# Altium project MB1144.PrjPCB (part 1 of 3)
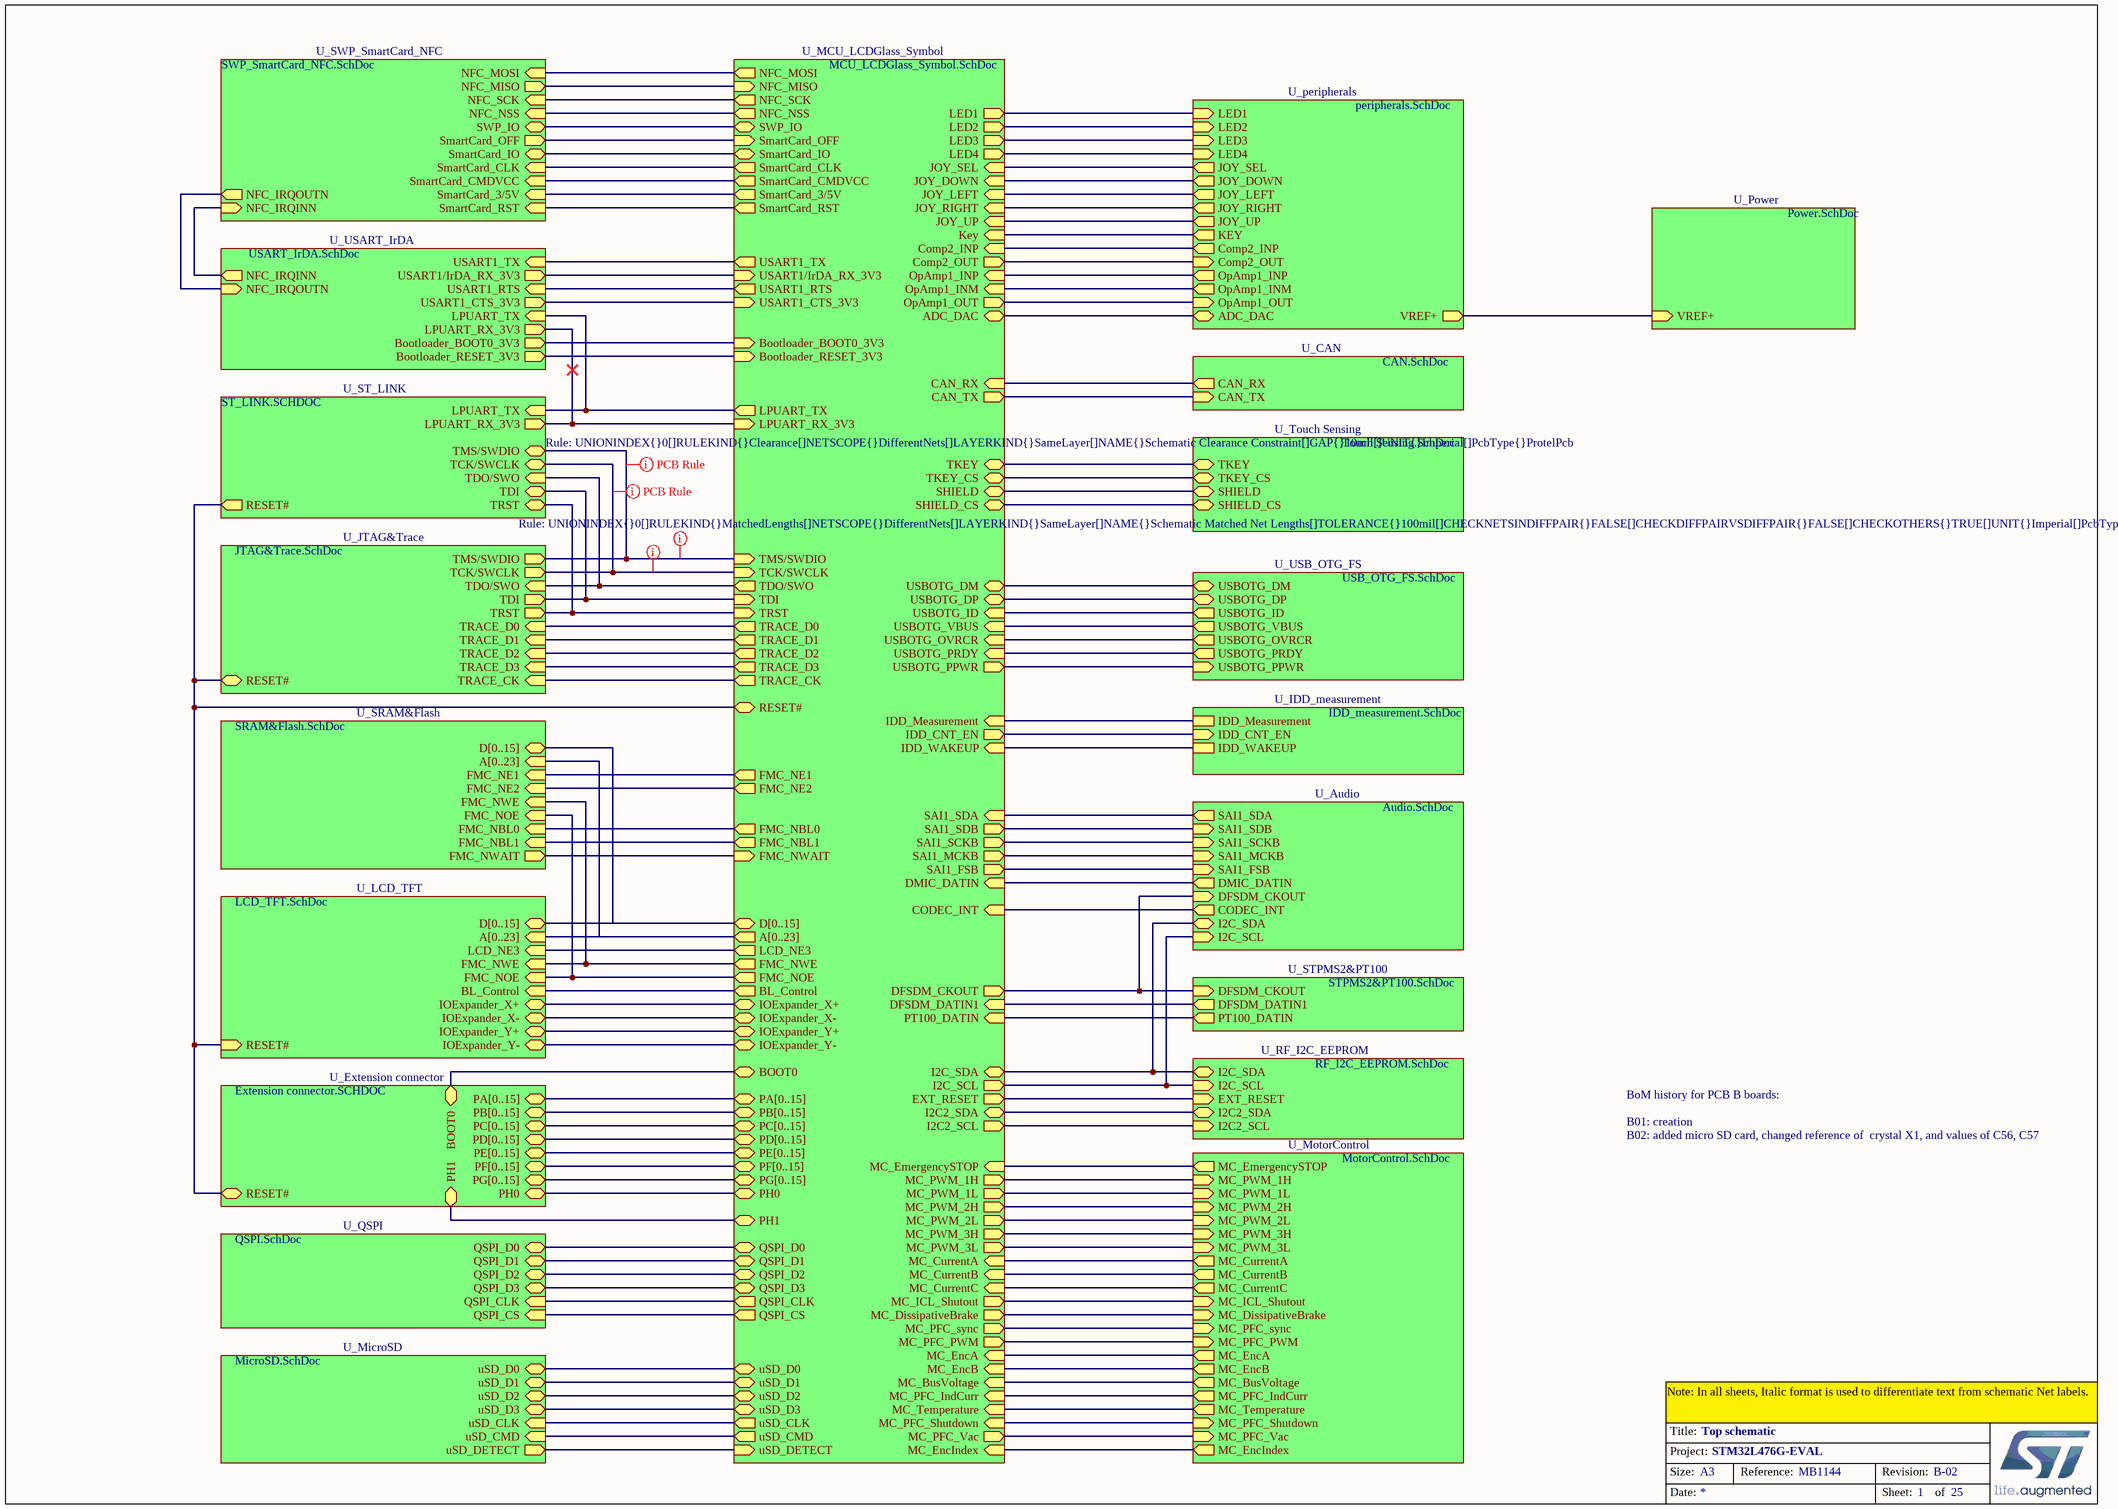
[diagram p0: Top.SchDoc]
25 sheets, 601 parts. Net scope: hierarchical (ports join the sheet entries above them; power ports are global).
Sheets:
  Top.SchDoc
    U_MCU_LCDGlass_Symbol = MCU_LCDGlass_Symbol.SchDoc
      U_MCU = MCU.SchDoc
      U_LCD_Glass = LCD_Glass.SchDoc
      U_IO_Expandor = IO_Expandor.SchDoc
      U_MCU2 = MCU2.SchDoc
    U_SRAM&Flash = SRAM&Flash.SchDoc
    U_MotorControl = MotorControl.SchDoc
    U_MicroSD = MicroSD.SchDoc
    U_QSPI = QSPI.SchDoc
    U_Extension connector = Extension connector.SCHDOC
    U_JTAG&Trace = JTAG&Trace.SchDoc
    U_ST_LINK = ST_LINK.SCHDOC
    U_USART_IrDA = USART_IrDA.SchDoc
    U_SWP_SmartCard_NFC = SWP_SmartCard_NFC.SchDoc
    U_STPMS2&PT100 = STPMS2&PT100.SchDoc
    U_IDD_measurement = IDD_measurement.SchDoc
    U_USB_OTG_FS = USB_OTG_FS.SchDoc
    U_Touch Sensing = Touch Sensing.SchDoc
    U_CAN = CAN.SchDoc
    U_peripherals = peripherals.SchDoc
    U_Power = Power.SchDoc
    U_Audio = Audio.SchDoc
    U_LCD_TFT = LCD_TFT.SchDoc
    U_RF_I2C_EEPROM = RF_I2C_EEPROM.SchDoc

## Sheet Top.SchDoc: Top schematic
size A3; DocumentNumber: MB1144; Revision: B-02; SheetNumber: 1; SheetTotal: 25; PageSetup: Record=PageOptions|CenterHorizontal=True|CenterVertical=True|PrintScale=1.01|XCorrection=1.00|YCorrection=1.00|PrintKind=1|BorderSize=5000000|LeftOffset=0|BottomOffset=0|Orientation=2|PaperLength=1000|PaperWidth=1000|Scale=100|PaperSource=264|PrintQuality=600|MediaType=1|DitherType=10|PaperKind=A3|PrintScaleMode=1; Project: STM32L476G-EVAL

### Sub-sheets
U_Audio = Audio.SchDoc: SAI1_SCKB (in), SAI1_FSB (in), SAI1_SDB (in), CODEC_INT (out), I2C_SCL (in), SAI1_MCKB (in), I2C_SDA (bidir), DMIC_DATIN (out), DFSDM_CKOUT (in), SAI1_SDA (out)
U_CAN = CAN.SchDoc: CAN_TX (in), CAN_RX (out)
U_Extension connector = Extension connector.SCHDOC: PA[0..15] (bidir), PB[0..15] (bidir), PC[0..15] (bidir), PD[0..15] (bidir), PE[0..15] (bidir), RESET# (bidir), PF[0..15] (bidir), PG[0..15] (bidir), PH1, PH0, BOOT0
U_IDD_measurement = IDD_measurement.SchDoc: IDD_Measurement, IDD_CNT_EN (in), IDD_WAKEUP
U_JTAG&Trace = JTAG&Trace.SchDoc: TDI (out), RESET# (bidir), TRACE_D3 (in), TRACE_D2 (in), TRACE_D1 (in), TRACE_D0 (in), TRACE_CK (in), TRST (out), TMS/SWDIO (out), TCK/SWCLK (out), TDO/SWO (in)
U_LCD_TFT = LCD_TFT.SchDoc: RESET# (in), FMC_NWE (in), LCD_NE3 (in), FMC_NOE (in), D[0..15] (bidir), A[0..23] (in), IOExpander_Y+ (bidir), IOExpander_Y- (bidir), IOExpander_X+ (bidir), IOExpander_X- (bidir), BL_Control (in)
U_MCU_LCDGlass_Symbol = MCU_LCDGlass_Symbol.SchDoc: FMC_NWAIT (in), FMC_NOE (out), FMC_NWE (out), FMC_NE1 (out), FMC_NE2 (out), LCD_NE3 (out), LED1 (out), LED2 (out), LPUART_TX (out), USART1_TX (out), USART1_RTS (out), TMS/SWDIO (in), TCK/SWCLK (in), TDI (in), TRST (in), Key (in), DFSDM_DATIN1 (in), IDD_Measurement (in), CODEC_INT (in), USBOTG_PRDY (in), USBOTG_OVRCR (in), DMIC_DATIN (in), PT100_DATIN (in), USBOTG_VBUS (in), USBOTG_ID (in), IDD_WAKEUP (in), OpAmp1_INM (in), Comp2_INP (in), TDO/SWO (out), TRACE_D1 (out), TRACE_D2 (out), TRACE_D3 (out), IDD_CNT_EN (out), USBOTG_PPWR (out), TRACE_CK (out), TRACE_D0 (out), SmartCard_CLK (out), OpAmp1_OUT (out), ADC_DAC (bidir), USBOTG_DP (bidir), USBOTG_DM (bidir), SmartCard_IO (bidir), QSPI_D0 (bidir), QSPI_D1 (bidir), QSPI_D2 (bidir), QSPI_D3 (bidir), uSD_D0 (bidir), uSD_D1 (bidir), uSD_D2 (bidir), uSD_D3 (bidir), MC_DissipativeBrake (out), MC_PFC_sync (out), MC_PWM_1H (out), MC_PWM_1L (out), MC_PWM_2H (out), MC_PWM_2L (out), MC_PWM_3H (out), MC_PWM_3L (out), MC_ICL_Shutout (out), MC_PFC_PWM (out), MC_PFC_Vac (out), QSPI_CLK (out), QSPI_CS (out), FMC_NBL0 (out), FMC_NBL1 (out), CAN_TX (out), MC_EncA (in), MC_EncB (in), MC_EncIndex (in), MC_CurrentB (in), MC_CurrentC (in), MC_Temperature (in), MC_PFC_Shutdown (in), CAN_RX (in), uSD_DETECT (in), uSD_CMD (out), uSD_CLK (out), SWP_IO (bidir), IOExpander_X+ (bidir), IOExpander_X- (bidir), IOExpander_Y+ (bidir), IOExpander_Y- (bidir), JOY_SEL (in), JOY_DOWN (in), JOY_LEFT (in), JOY_RIGHT (in), JOY_UP (in), SmartCard_OFF (in), LED4 (out), LED3 (out), SmartCard_RST (out), SmartCard_CMDVCC (out), SmartCard_3/5V (out), D[0..15] (bidir), A[0..23] (out), PA[0..15] (bidir), PB[0..15] (bidir), PC[0..15] (bidir), PD[0..15] (bidir), PE[0..15] (bidir), PF[0..15] (bidir), PG[0..15] (bidir), MC_CurrentA (in), MC_EmergencySTOP (in), MC_BusVoltage (in), MC_PFC_IndCurr (in), RESET# (bidir), DFSDM_CKOUT (out), I2C_SCL (out), I2C_SDA (bidir), PH1, PH0, SHIELD, SAI1_MCKB (out), SAI1_SCKB (out), SAI1_FSB (out), SAI1_SDB (out), SAI1_SDA (in), OpAmp1_INP (in), Comp2_OUT (out), TKEY, TKEY_CS, SHIELD_CS, Bootloader_RESET_3V3 (in), Bootloader_BOOT0_3V3 (in), LPUART_RX_3V3 (in), USART1_CTS_3V3 (in), USART1/IrDA_RX_3V3 (in), BL_Control (out), EXT_RESET (out), BOOT0, NFC_NSS (out), NFC_MOSI (out), NFC_SCK (out), NFC_MISO (in), I2C2_SDA (bidir), I2C2_SCL (out)
U_MicroSD = MicroSD.SchDoc: uSD_CLK (in), uSD_CMD (in), uSD_D0 (bidir), uSD_D1 (bidir), uSD_D2 (bidir), uSD_D3 (bidir), uSD_DETECT (out)
U_MotorControl = MotorControl.SchDoc: MC_EmergencySTOP (out), MC_CurrentA (out), MC_CurrentB (out), MC_CurrentC (out), MC_PFC_sync (in), MC_PWM_3L (in), MC_PWM_2H (in), MC_PWM_2L (in), MC_PWM_1H (in), MC_PWM_1L (in), MC_PWM_3H (in), MC_ICL_Shutout (in), MC_DissipativeBrake (in), MC_PFC_PWM (in), MC_EncA (out), MC_EncB (out), MC_BusVoltage (out), MC_EncIndex (out), MC_PFC_IndCurr (out), MC_Temperature (out), MC_PFC_Shutdown (in), MC_PFC_Vac (in)
U_peripherals = peripherals.SchDoc: ADC_DAC (bidir), LED4 (in), LED3 (in), LED1 (in), LED2 (in), JOY_SEL (out), JOY_DOWN (out), JOY_LEFT (out), JOY_RIGHT (out), JOY_UP (out), KEY (out), VREF+ (out), Comp2_INP (out), OpAmp1_OUT (in), OpAmp1_INM (out), OpAmp1_INP (out), Comp2_OUT (in)
U_Power = Power.SchDoc: VREF+ (in)
U_QSPI = QSPI.SchDoc: QSPI_D0 (bidir), QSPI_D3 (bidir), QSPI_D2 (bidir), QSPI_D1 (bidir), QSPI_CLK (in), QSPI_CS (in)
U_RF_I2C_EEPROM = RF_I2C_EEPROM.SchDoc: I2C_SCL (in), I2C_SDA (bidir), EXT_RESET (in), I2C2_SDA (bidir), I2C2_SCL (in)
U_SRAM&Flash = SRAM&Flash.SchDoc: FMC_NWE (in), FMC_NOE (in), FMC_NWAIT (out), FMC_NBL0 (in), FMC_NBL1 (in), D[0..15] (bidir), A[0..23] (in), FMC_NE1 (in), FMC_NE2 (in)
U_ST_LINK = ST_LINK.SCHDOC: TDO/SWO (in), RESET# (out), TDI, TRST, TMS/SWDIO, TCK/SWCLK, LPUART_RX_3V3 (out), LPUART_TX (in)
U_STPMS2&PT100 = STPMS2&PT100.SchDoc: DFSDM_CKOUT (in), DFSDM_DATIN1 (out), PT100_DATIN (out)
U_SWP_SmartCard_NFC = SWP_SmartCard_NFC.SchDoc: SWP_IO (bidir), SmartCard_3/5V (in), SmartCard_IO (bidir), SmartCard_RST (in), SmartCard_CLK (in), SmartCard_OFF (out), SmartCard_CMDVCC (in), NFC_IRQINN (in), NFC_IRQOUTN (out), NFC_NSS (in), NFC_MOSI (in), NFC_MISO (out), NFC_SCK (in)
U_Touch Sensing = Touch Sensing.SchDoc: SHIELD, SHIELD_CS, TKEY_CS, TKEY
U_USART_IrDA = USART_IrDA.SchDoc: USART1/IrDA_RX_3V3 (out), Bootloader_BOOT0_3V3 (out), Bootloader_RESET_3V3 (out), USART1_CTS_3V3 (out), USART1_TX (in), USART1_RTS (in), LPUART_RX_3V3 (out), LPUART_TX (in), NFC_IRQINN (out), NFC_IRQOUTN (in)
U_USB_OTG_FS = USB_OTG_FS.SchDoc: USBOTG_VBUS (out), USBOTG_PRDY (out), USBOTG_DM (bidir), USBOTG_DP (bidir), USBOTG_OVRCR (out), USBOTG_PPWR (in), USBOTG_ID (out)

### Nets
BOOT0: sheet U_MCU_LCDGlass_Symbol/BOOT0, sheet U_Extension connector/BOOT0
Comp2_INP: sheet U_MCU_LCDGlass_Symbol/Comp2_INP, sheet U_peripherals/Comp2_INP
Comp2_OUT: sheet U_MCU_LCDGlass_Symbol/Comp2_OUT, sheet U_peripherals/Comp2_OUT
I2C_SCL: sheet U_MCU_LCDGlass_Symbol/I2C_SCL, sheet U_Audio/I2C_SCL, sheet U_RF_I2C_EEPROM/I2C_SCL
I2C_SDA: sheet U_MCU_LCDGlass_Symbol/I2C_SDA, sheet U_Audio/I2C_SDA, sheet U_RF_I2C_EEPROM/I2C_SDA
LCD_NE3: sheet U_MCU_LCDGlass_Symbol/LCD_NE3, sheet U_LCD_TFT/LCD_NE3
LCDSEG7: sheet U_MCU_LCDGlass_Symbol/TDO/SWO, sheet U_JTAG&Trace/TDO/SWO, sheet U_ST_LINK/TDO/SWO
LCDSEG8: sheet U_MCU_LCDGlass_Symbol/TRST, sheet U_JTAG&Trace/TRST, sheet U_ST_LINK/TRST
LCDSEG17: sheet U_MCU_LCDGlass_Symbol/TDI, sheet U_JTAG&Trace/TDI, sheet U_ST_LINK/TDI
OpAmp1_INM: sheet U_MCU_LCDGlass_Symbol/OpAmp1_INM, sheet U_peripherals/OpAmp1_INM
OpAmp1_INP: sheet U_MCU_LCDGlass_Symbol/OpAmp1_INP, sheet U_peripherals/OpAmp1_INP
OpAmp1_OUT: sheet U_MCU_LCDGlass_Symbol/OpAmp1_OUT, sheet U_peripherals/OpAmp1_OUT
PA4: sheet U_MCU_LCDGlass_Symbol/ADC_DAC, sheet U_peripherals/ADC_DAC
PA11: sheet U_MCU_LCDGlass_Symbol/USBOTG_DM, sheet U_USB_OTG_FS/USBOTG_DM
PA12: sheet U_MCU_LCDGlass_Symbol/USBOTG_DP, sheet U_USB_OTG_FS/USBOTG_DP
PA13: sheet U_MCU_LCDGlass_Symbol/TMS/SWDIO, sheet U_JTAG&Trace/TMS/SWDIO, sheet U_ST_LINK/TMS/SWDIO
PA14: sheet U_MCU_LCDGlass_Symbol/TCK/SWCLK, sheet U_JTAG&Trace/TCK/SWCLK, sheet U_ST_LINK/TCK/SWCLK
PB6: sheet U_MCU_LCDGlass_Symbol/USART1_TX, sheet U_USART_IrDA/USART1_TX
PC13: sheet U_MCU_LCDGlass_Symbol/Key, sheet U_peripherals/KEY
PD3: sheet U_MCU_LCDGlass_Symbol/DFSDM_DATIN1, sheet U_STPMS2&PT100/DFSDM_DATIN1
PD4: sheet U_MCU_LCDGlass_Symbol/FMC_NOE, sheet U_SRAM&Flash/FMC_NOE, sheet U_LCD_TFT/FMC_NOE
PD5: sheet U_MCU_LCDGlass_Symbol/FMC_NWE, sheet U_SRAM&Flash/FMC_NWE, sheet U_LCD_TFT/FMC_NWE
PD7: sheet U_MCU_LCDGlass_Symbol/FMC_NE1, sheet U_SRAM&Flash/FMC_NE1
PF11: sheet U_MCU_LCDGlass_Symbol/NFC_NSS, sheet U_SWP_SmartCard_NFC/NFC_NSS
PG8: sheet U_MCU_LCDGlass_Symbol/LPUART_RX_3V3, sheet U_ST_LINK/LPUART_RX_3V3, sheet U_USART_IrDA/LPUART_RX_3V3
PG9: sheet U_MCU_LCDGlass_Symbol/FMC_NE2, sheet U_SRAM&Flash/FMC_NE2
PG11: sheet U_MCU_LCDGlass_Symbol/USART1_CTS_3V3, sheet U_USART_IrDA/USART1_CTS_3V3
PG12: sheet U_MCU_LCDGlass_Symbol/USART1_RTS, sheet U_USART_IrDA/USART1_RTS
PH0: sheet U_MCU_LCDGlass_Symbol/PH0, sheet U_Extension connector/PH0
PH1: sheet U_MCU_LCDGlass_Symbol/PH1, sheet U_Extension connector/PH1
RESET#: sheet U_MCU_LCDGlass_Symbol/RESET#, sheet U_Extension connector/RESET#, sheet U_JTAG&Trace/RESET#, sheet U_ST_LINK/RESET#, sheet U_LCD_TFT/RESET#
NetB3_1: sheet U_MCU_LCDGlass_Symbol/JOY_LEFT, sheet U_peripherals/JOY_LEFT
NetB3_2: sheet U_MCU_LCDGlass_Symbol/JOY_SEL, sheet U_peripherals/JOY_SEL
NetB3_3: sheet U_MCU_LCDGlass_Symbol/JOY_DOWN, sheet U_peripherals/JOY_DOWN
NetB3_4: sheet U_MCU_LCDGlass_Symbol/JOY_RIGHT, sheet U_peripherals/JOY_RIGHT
NetB3_6: sheet U_MCU_LCDGlass_Symbol/JOY_UP, sheet U_peripherals/JOY_UP
NetC1_2: sheet U_MCU_LCDGlass_Symbol/MC_EncB, sheet U_MotorControl/MC_EncB
NetC2_2: sheet U_MCU_LCDGlass_Symbol/MC_EncIndex, sheet U_MotorControl/MC_EncIndex
NetC3_1: sheet U_MCU_LCDGlass_Symbol/MC_PFC_IndCurr, sheet U_MotorControl/MC_PFC_IndCurr
NetC4_2: sheet U_MCU_LCDGlass_Symbol/MC_EncA, sheet U_MotorControl/MC_EncA
NetC5_2: sheet U_MCU_LCDGlass_Symbol/MC_PFC_Shutdown, sheet U_MotorControl/MC_PFC_Shutdown
NetC6_2: sheet U_MCU_LCDGlass_Symbol/MC_PFC_Vac, sheet U_MotorControl/MC_PFC_Vac
NetC7_2: sheet U_MCU_LCDGlass_Symbol/MC_EmergencySTOP, sheet U_MotorControl/MC_EmergencySTOP
NetC9_2: sheet U_MCU_LCDGlass_Symbol/MC_PFC_PWM, sheet U_MotorControl/MC_PFC_PWM
NetC10_2: sheet U_MCU_LCDGlass_Symbol/MC_CurrentC, sheet U_MotorControl/MC_CurrentC
NetC11_1: sheet U_MCU_LCDGlass_Symbol/MC_BusVoltage, sheet U_MotorControl/MC_BusVoltage
NetC13_2: sheet U_MCU_LCDGlass_Symbol/MC_CurrentB, sheet U_MotorControl/MC_CurrentB
NetC14_2: sheet U_MCU_LCDGlass_Symbol/MC_CurrentA, sheet U_MotorControl/MC_CurrentA
NetC15_1: sheet U_MCU_LCDGlass_Symbol/USBOTG_PRDY, sheet U_MCU_LCDGlass_Symbol/USBOTG_VBUS, sheet U_USB_OTG_FS/USBOTG_VBUS, sheet U_USB_OTG_FS/USBOTG_PRDY
NetC16_2: sheet U_MCU_LCDGlass_Symbol/MC_PFC_sync, sheet U_MotorControl/MC_PFC_sync
NetC17_1: sheet U_MCU_LCDGlass_Symbol/MC_Temperature, sheet U_MotorControl/MC_Temperature
NetC34_2: sheet U_MCU_LCDGlass_Symbol/SHIELD_CS, sheet U_Touch Sensing/SHIELD_CS
NetC37_2: sheet U_MCU_LCDGlass_Symbol/TKEY_CS, sheet U_Touch Sensing/TKEY_CS
NetC52_2: sheet U_peripherals/VREF+, sheet U_Power/VREF+
NetC73_1: sheet U_MCU_LCDGlass_Symbol/IDD_Measurement, sheet U_IDD_measurement/IDD_Measurement
NetCN2_3: sheet U_MCU_LCDGlass_Symbol/MC_PWM_1H, sheet U_MotorControl/MC_PWM_1H
NetCN2_5: sheet U_MCU_LCDGlass_Symbol/MC_PWM_1L, sheet U_MotorControl/MC_PWM_1L
NetCN2_7: sheet U_MCU_LCDGlass_Symbol/MC_PWM_2H, sheet U_MotorControl/MC_PWM_2H
NetCN2_9: sheet U_MCU_LCDGlass_Symbol/MC_PWM_2L, sheet U_MotorControl/MC_PWM_2L
NetCN2_11: sheet U_MCU_LCDGlass_Symbol/MC_PWM_3H, sheet U_MotorControl/MC_PWM_3H
NetCN2_13: sheet U_MCU_LCDGlass_Symbol/MC_PWM_3L, sheet U_MotorControl/MC_PWM_3L
NetCN2_21: sheet U_MCU_LCDGlass_Symbol/MC_ICL_Shutout, sheet U_MotorControl/MC_ICL_Shutout
NetCN2_23: sheet U_MCU_LCDGlass_Symbol/MC_DissipativeBrake, sheet U_MotorControl/MC_DissipativeBrake
NetCN3_4: sheet U_MCU_LCDGlass_Symbol/EXT_RESET, sheet U_RF_I2C_EEPROM/EXT_RESET
NetCN11_4: sheet U_MCU_LCDGlass_Symbol/uSD_DETECT, sheet U_MicroSD/uSD_DETECT
NetCN11_6: sheet U_MCU_LCDGlass_Symbol/USBOTG_ID, sheet U_USB_OTG_FS/USBOTG_ID
NetCN11_8: sheet U_MCU_LCDGlass_Symbol/CAN_TX, sheet U_CAN/CAN_TX
NetCN11_16: sheet U_MCU_LCDGlass_Symbol/NFC_MISO, sheet U_SWP_SmartCard_NFC/NFC_MISO
NetCN11_18: sheet U_MCU_LCDGlass_Symbol/NFC_SCK, sheet U_SWP_SmartCard_NFC/NFC_SCK
NetCN11_20: sheet U_MCU_LCDGlass_Symbol/SWP_IO, sheet U_SWP_SmartCard_NFC/SWP_IO
NetCN11_24: sheet U_MCU_LCDGlass_Symbol/CAN_RX, sheet U_CAN/CAN_RX
NetCN11_26: sheet U_MCU_LCDGlass_Symbol/NFC_MOSI, sheet U_SWP_SmartCard_NFC/NFC_MOSI
NetCN11_28: sheet U_MCU_LCDGlass_Symbol/DFSDM_CKOUT, sheet U_STPMS2&PT100/DFSDM_CKOUT, sheet U_Audio/DFSDM_CKOUT
NetCN11_30: sheet U_MCU_LCDGlass_Symbol/LED3, sheet U_peripherals/LED3
NetCN11_32: sheet U_MCU_LCDGlass_Symbol/DMIC_DATIN, sheet U_Audio/DMIC_DATIN
NetCN12_12: sheet U_MCU_LCDGlass_Symbol/TRACE_CK, sheet U_JTAG&Trace/TRACE_CK
NetCN12_18: sheet U_MCU_LCDGlass_Symbol/TRACE_D2, sheet U_JTAG&Trace/TRACE_D2
NetCN12_20: sheet U_MCU_LCDGlass_Symbol/TRACE_D3, sheet U_JTAG&Trace/TRACE_D3
NetCN13_1: sheet U_USART_IrDA/NFC_IRQOUTN, sheet U_SWP_SmartCard_NFC/NFC_IRQOUTN
NetCN13_2: sheet U_USART_IrDA/NFC_IRQINN, sheet U_SWP_SmartCard_NFC/NFC_IRQINN
NetCN14_2: sheet U_MCU_LCDGlass_Symbol/uSD_CMD, sheet U_MicroSD/uSD_CMD
NetCN14_10: sheet U_MCU_LCDGlass_Symbol/USART1/IrDA_RX_3V3, sheet U_USART_IrDA/USART1/IrDA_RX_3V3
NetCN14_40: sheet U_MCU_LCDGlass_Symbol/FMC_NBL0, sheet U_SRAM&Flash/FMC_NBL0
NetCN14_42: sheet U_MCU_LCDGlass_Symbol/FMC_NBL1, sheet U_SRAM&Flash/FMC_NBL1
NetCN18_1: sheet U_MCU_LCDGlass_Symbol/uSD_D2, sheet U_MicroSD/uSD_D2
NetCN18_2: sheet U_MCU_LCDGlass_Symbol/uSD_D3, sheet U_MicroSD/uSD_D3
NetCN18_5: sheet U_MCU_LCDGlass_Symbol/uSD_CLK, sheet U_MicroSD/uSD_CLK
NetCN18_7: sheet U_MCU_LCDGlass_Symbol/uSD_D0, sheet U_MicroSD/uSD_D0
NetCN18_8: sheet U_MCU_LCDGlass_Symbol/uSD_D1, sheet U_MicroSD/uSD_D1
NetCN19_31: sheet U_MCU_LCDGlass_Symbol/IOExpander_X-, sheet U_LCD_TFT/IOExpander_X-
NetCN19_32: sheet U_MCU_LCDGlass_Symbol/IOExpander_X+, sheet U_LCD_TFT/IOExpander_X+
NetCN19_33: sheet U_MCU_LCDGlass_Symbol/IOExpander_Y-, sheet U_LCD_TFT/IOExpander_Y-
NetCN19_34: sheet U_MCU_LCDGlass_Symbol/IOExpander_Y+, sheet U_LCD_TFT/IOExpander_Y+
NetD4_2: sheet U_MCU_LCDGlass_Symbol/Bootloader_RESET_3V3, sheet U_USART_IrDA/Bootloader_RESET_3V3
NetJP19_1: sheet U_MCU_LCDGlass_Symbol/USBOTG_PPWR, sheet U_USB_OTG_FS/USBOTG_PPWR
NetLD6_2: sheet U_MCU_LCDGlass_Symbol/USBOTG_OVRCR, sheet U_USB_OTG_FS/USBOTG_OVRCR
NetR24_1: sheet U_MCU_LCDGlass_Symbol/PT100_DATIN, sheet U_STPMS2&PT100/PT100_DATIN
NetR32_2: sheet U_MCU_LCDGlass_Symbol/FMC_NWAIT, sheet U_SRAM&Flash/FMC_NWAIT
NetR34_1: sheet U_MCU_LCDGlass_Symbol/LPUART_TX, sheet U_ST_LINK/LPUART_TX, sheet U_USART_IrDA/LPUART_TX
NetR35_1: sheet U_MCU_LCDGlass_Symbol/CODEC_INT, sheet U_Audio/CODEC_INT
NetR37_1: sheet U_MCU_LCDGlass_Symbol/SHIELD, sheet U_Touch Sensing/SHIELD
NetR39_1: sheet U_MCU_LCDGlass_Symbol/TKEY, sheet U_Touch Sensing/TKEY
NetR53_2: sheet U_MCU_LCDGlass_Symbol/SAI1_SDA, sheet U_Audio/SAI1_SDA
NetR54_2: sheet U_MCU_LCDGlass_Symbol/LED1, sheet U_peripherals/LED1
NetR59_2: sheet U_MCU_LCDGlass_Symbol/Bootloader_BOOT0_3V3, sheet U_USART_IrDA/Bootloader_BOOT0_3V3
NetR71_2: sheet U_MCU_LCDGlass_Symbol/QSPI_CS, sheet U_QSPI/QSPI_CS
NetR89_1: sheet U_MCU_LCDGlass_Symbol/SAI1_SCKB, sheet U_Audio/SAI1_SCKB
NetR90_1: sheet U_MCU_LCDGlass_Symbol/SAI1_FSB, sheet U_Audio/SAI1_FSB
NetR91_1: sheet U_MCU_LCDGlass_Symbol/IDD_CNT_EN, sheet U_IDD_measurement/IDD_CNT_EN
NetR104_1: sheet U_MCU_LCDGlass_Symbol/TRACE_D0, sheet U_JTAG&Trace/TRACE_D0
NetR105_1: sheet U_MCU_LCDGlass_Symbol/SAI1_SDB, sheet U_Audio/SAI1_SDB
NetR106_1: sheet U_MCU_LCDGlass_Symbol/SAI1_MCKB, sheet U_Audio/SAI1_MCKB
NetR107_1: sheet U_MCU_LCDGlass_Symbol/SmartCard_CLK, sheet U_SWP_SmartCard_NFC/SmartCard_CLK
NetR137_1: sheet U_MCU_LCDGlass_Symbol/IDD_WAKEUP, sheet U_IDD_measurement/IDD_WAKEUP
NetR143_1: sheet U_MCU_LCDGlass_Symbol/SmartCard_IO, sheet U_SWP_SmartCard_NFC/SmartCard_IO
NetR156_2: sheet U_MCU_LCDGlass_Symbol/TRACE_D1, sheet U_JTAG&Trace/TRACE_D1
NetR213_1: sheet U_MCU_LCDGlass_Symbol/SmartCard_OFF, sheet U_SWP_SmartCard_NFC/SmartCard_OFF
NetR214_2: sheet U_MCU_LCDGlass_Symbol/SmartCard_RST, sheet U_SWP_SmartCard_NFC/SmartCard_RST
NetR215_2: sheet U_MCU_LCDGlass_Symbol/SmartCard_CMDVCC, sheet U_SWP_SmartCard_NFC/SmartCard_CMDVCC
NetR241_1: sheet U_MCU_LCDGlass_Symbol/SmartCard_3/5V, sheet U_SWP_SmartCard_NFC/SmartCard_3/5V
NetR255_1: sheet U_MCU_LCDGlass_Symbol/LED4, sheet U_peripherals/LED4
NetR257_1: sheet U_MCU_LCDGlass_Symbol/LED2, sheet U_peripherals/LED2
NetR260_1: sheet U_MCU_LCDGlass_Symbol/BL_Control, sheet U_LCD_TFT/BL_Control
NetR263_2: sheet U_MCU_LCDGlass_Symbol/I2C2_SDA, sheet U_RF_I2C_EEPROM/I2C2_SDA
NetR264_2: sheet U_MCU_LCDGlass_Symbol/I2C2_SCL, sheet U_RF_I2C_EEPROM/I2C2_SCL
NetSB9_1: sheet U_MCU_LCDGlass_Symbol/QSPI_CLK, sheet U_QSPI/QSPI_CLK
NetSB12_1: sheet U_MCU_LCDGlass_Symbol/QSPI_D0, sheet U_QSPI/QSPI_D0
NetSB14_1: sheet U_MCU_LCDGlass_Symbol/QSPI_D1, sheet U_QSPI/QSPI_D1
NetSB18_1: sheet U_MCU_LCDGlass_Symbol/QSPI_D2, sheet U_QSPI/QSPI_D2
NetSB21_1: sheet U_MCU_LCDGlass_Symbol/QSPI_D3, sheet U_QSPI/QSPI_D3

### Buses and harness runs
bus sheet U_Extension connector/PA[0..15] = sheet U_MCU_LCDGlass_Symbol/PA[0..15]
bus sheet U_Extension connector/PB[0..15] = sheet U_MCU_LCDGlass_Symbol/PB[0..15]
bus sheet U_Extension connector/PC[0..15] = sheet U_MCU_LCDGlass_Symbol/PC[0..15]
bus sheet U_Extension connector/PD[0..15] = sheet U_MCU_LCDGlass_Symbol/PD[0..15]
bus sheet U_Extension connector/PE[0..15] = sheet U_MCU_LCDGlass_Symbol/PE[0..15]
bus sheet U_Extension connector/PF[0..15] = sheet U_MCU_LCDGlass_Symbol/PF[0..15]
bus sheet U_Extension connector/PG[0..15] = sheet U_MCU_LCDGlass_Symbol/PG[0..15]
bus sheet U_LCD_TFT/A[0..23] = sheet U_MCU_LCDGlass_Symbol/A[0..23] = sheet U_SRAM&Flash/A[0..23]
bus sheet U_LCD_TFT/D[0..15] = sheet U_MCU_LCDGlass_Symbol/D[0..15] = sheet U_SRAM&Flash/D[0..15]

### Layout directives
rule Matched Net Lengths [Tolerance = 100mil]: PA13, PA14
rule Clearance Constraint [Clearance = 10mil]: PA13, PA14

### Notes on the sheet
- BoM history for PCB B boards:
  B01: creation
  B02: added micro SD card, changed reference of  crystal X1, and values of C56, C57
- Note: In all sheets, Italic format is used to differentiate text from schematic Net labels.

## Sheet MCU_LCDGlass_Symbol.SchDoc: MCU_LCDGlassl
size A3; DocumentNumber: MB1144; Revision: B-02; SheetNumber: 2; SheetTotal: 25; PageSetup: Record=PageOptions|CenterHorizontal=True|CenterVertical=True|PrintScale=1.01|XCorrection=1.00|YCorrection=1.00|PrintKind=1|BorderSize=5000000|LeftOffset=0|BottomOffset=0|Orientation=2|PaperLength=1000|PaperWidth=1000|Scale=100|PaperSource=264|PrintQuality=600|MediaType=1|DitherType=10|PaperKind=A3|PrintScaleMode=1; Project: STM32L476G-EVAL
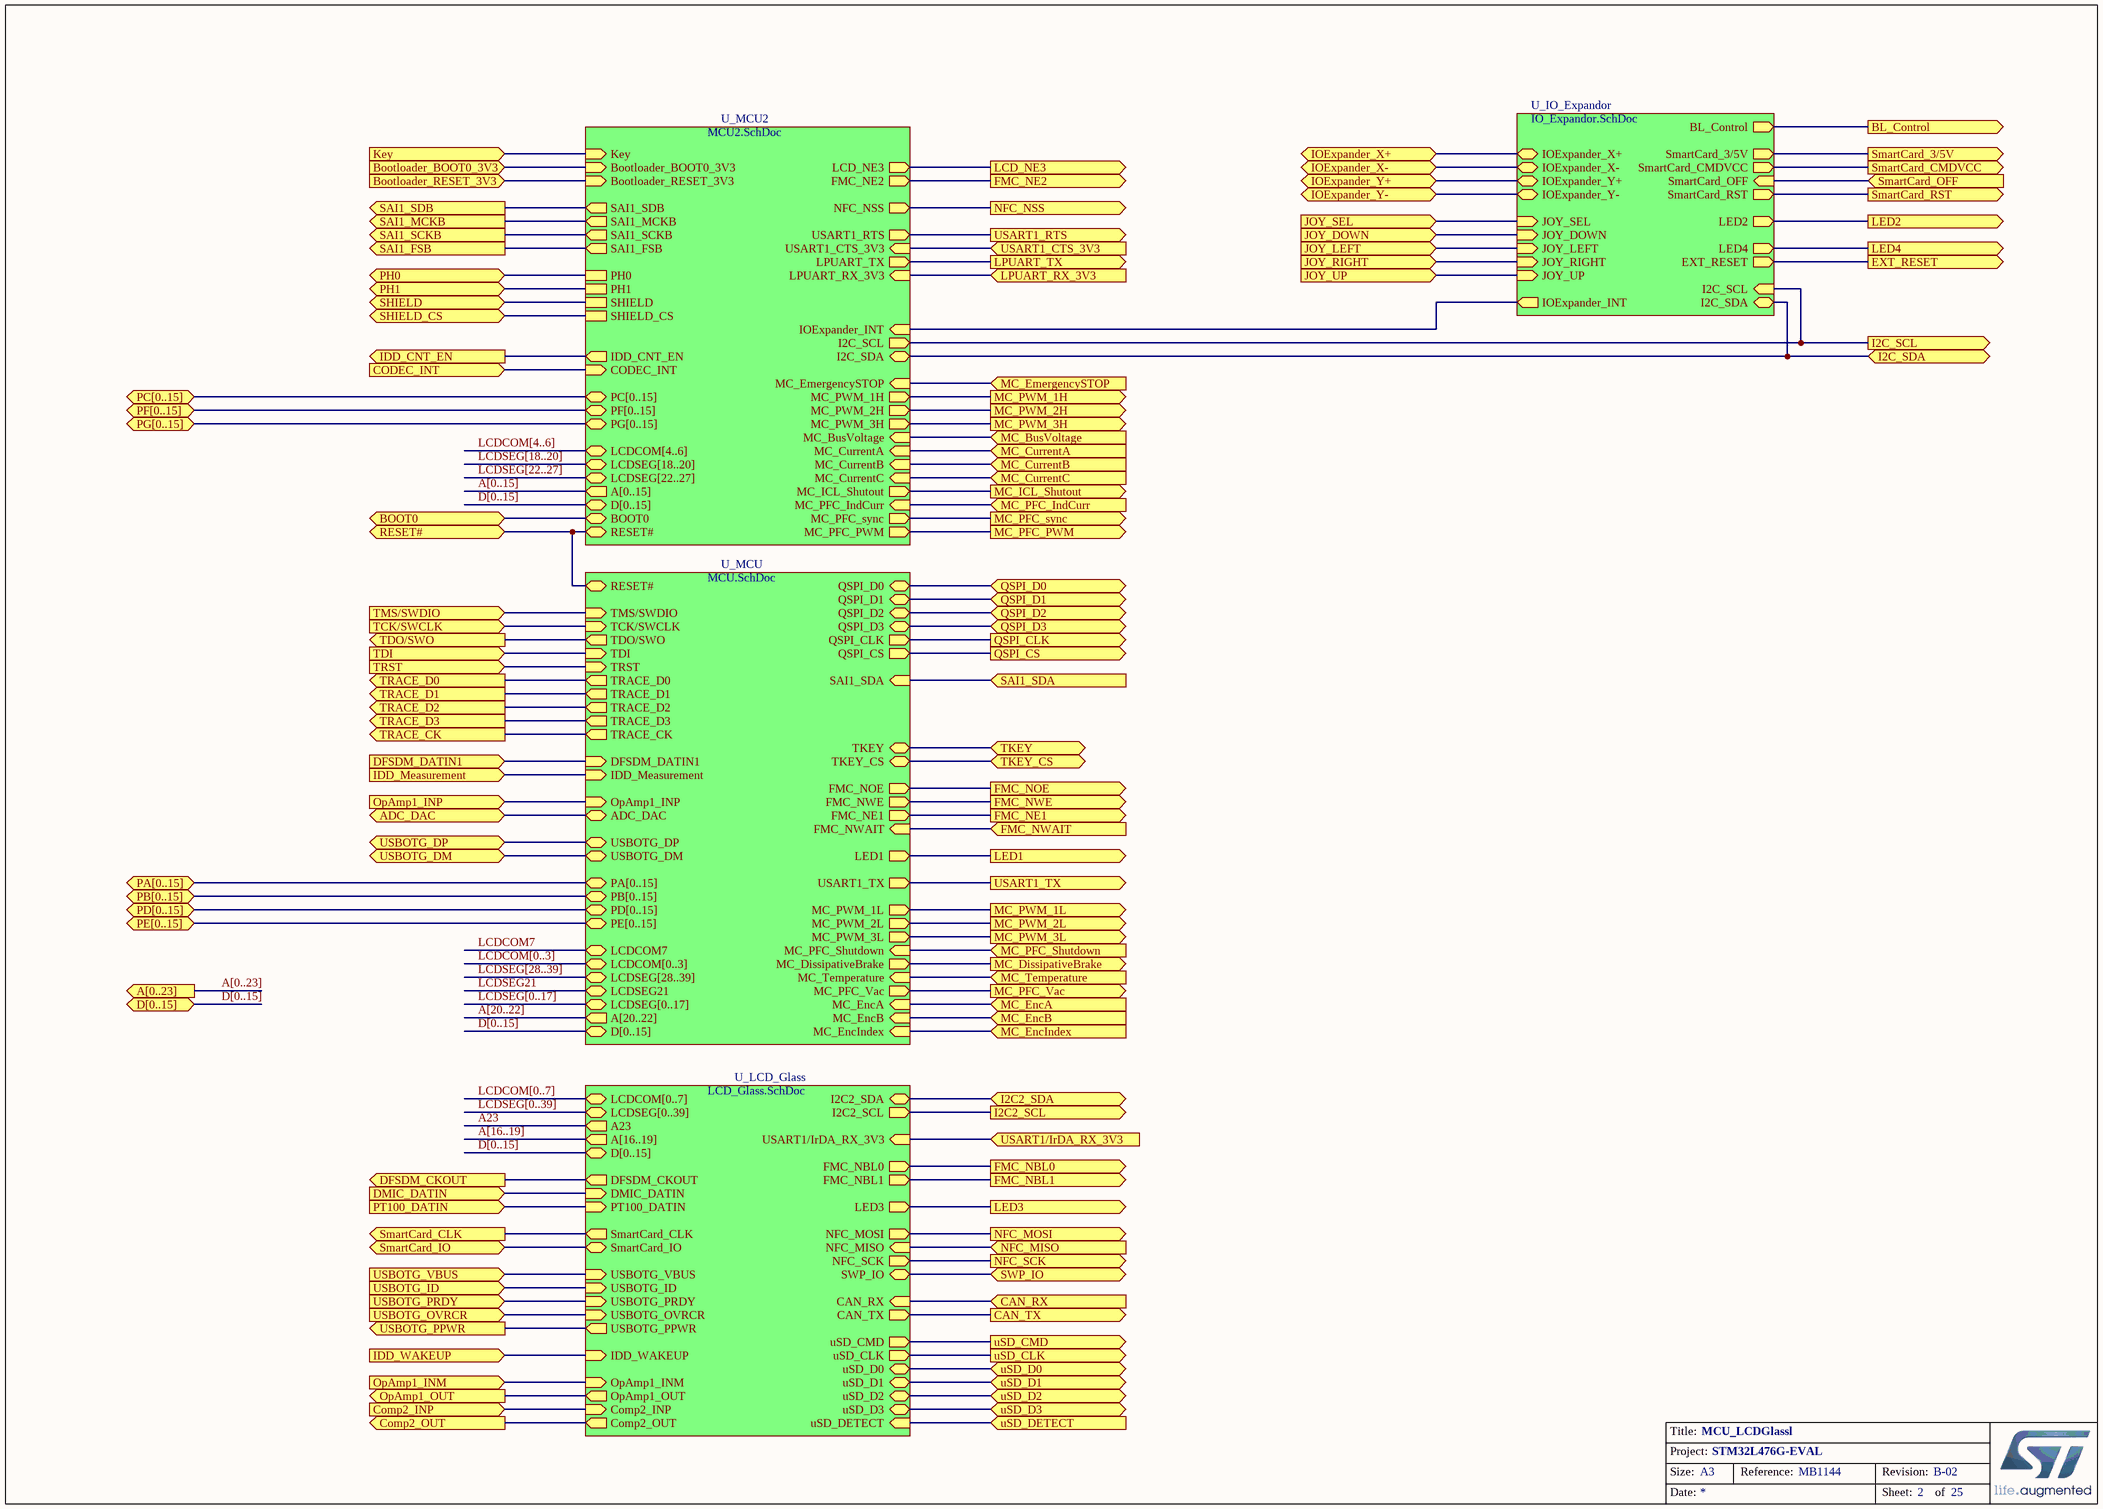
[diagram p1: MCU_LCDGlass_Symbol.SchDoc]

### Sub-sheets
U_IO_Expandor = IO_Expandor.SchDoc: IOExpander_Y+ (bidir), IOExpander_Y- (bidir), IOExpander_X+ (bidir), IOExpander_X- (bidir), IOExpander_INT (out), I2C_SDA (bidir), JOY_SEL (in), JOY_DOWN (in), JOY_LEFT (in), JOY_RIGHT (in), JOY_UP (in), LED4 (out), SmartCard_RST (out), SmartCard_CMDVCC (out), SmartCard_3/5V (out), SmartCard_OFF (in), I2C_SCL (in), LED2 (out), BL_Control (out), EXT_RESET (out)
U_LCD_Glass = LCD_Glass.SchDoc: uSD_CMD (out), uSD_CLK (out), uSD_D3 (bidir), uSD_D2 (bidir), IDD_WAKEUP (in), PT100_DATIN (in), uSD_D0 (bidir), uSD_D1 (bidir), OpAmp1_INM (in), FMC_NBL0 (out), FMC_NBL1 (out), LCDSEG[0..39] (bidir), LCDCOM[0..7] (bidir), USBOTG_VBUS (in), USBOTG_ID (in), CAN_TX (out), SWP_IO (bidir), CAN_RX (in), DMIC_DATIN (in), OpAmp1_OUT (out), Comp2_INP (in), SmartCard_CLK (out), SmartCard_IO (bidir), uSD_DETECT (in), DFSDM_CKOUT (out), D[0..15] (bidir), USBOTG_PRDY (in), USBOTG_OVRCR (in), USBOTG_PPWR (out), Comp2_OUT (out), USART1/IrDA_RX_3V3 (in), A[16..19] (out), A23 (out), NFC_MISO (in), NFC_SCK (out), NFC_MOSI (out), I2C2_SDA (bidir), I2C2_SCL (out), LED3 (out)
U_MCU = MCU.SchDoc: PA[0..15] (bidir), PB[0..15] (bidir), PD[0..15] (bidir), PE[0..15] (bidir), USBOTG_DM (bidir), USBOTG_DP (bidir), TMS/SWDIO (in), TCK/SWCLK (in), DFSDM_DATIN1 (in), FMC_NOE (out), FMC_NWE (out), FMC_NWAIT (in), FMC_NE1 (out), TRACE_D3 (out), TRACE_D1 (out), TRST (in), D[0..15] (bidir), IDD_Measurement (in), USART1_TX (out), LED1 (out), MC_DissipativeBrake (out), TRACE_D2 (out), MC_EncA (in), TDI (in), TDO/SWO (out), ADC_DAC (bidir), RESET# (bidir), QSPI_D3 (bidir), QSPI_D2 (bidir), QSPI_D1 (bidir), QSPI_D0 (bidir), QSPI_CLK (out), QSPI_CS (out), TRACE_D0 (out), TRACE_CK (out), SAI1_SDA (in), OpAmp1_INP (in), MC_PFC_Vac (out), MC_Temperature (in), MC_EncB (in), MC_EncIndex (in), TKEY, TKEY_CS, MC_PWM_1L (out), MC_PWM_2L (out), MC_PWM_3L (out), MC_PFC_Shutdown (in), A[20..22] (out), LCDCOM[0..3] (bidir), LCDCOM7, LCDSEG[0..17] (bidir), LCDSEG[28..39] (bidir), LCDSEG21 (bidir)
U_MCU2 = MCU2.SchDoc: PC[0..15] (bidir), Bootloader_BOOT0_3V3 (in), Bootloader_RESET_3V3 (in), Key (in), CODEC_INT (in), USART1_CTS_3V3 (in), FMC_NE2 (out), USART1_RTS (out), PF[0..15] (bidir), PG[0..15] (bidir), D[0..15] (bidir), MC_PFC_sync (out), IDD_CNT_EN (out), LPUART_TX (out), LPUART_RX_3V3 (in), LCD_NE3 (out), IOExpander_INT (in), I2C_SCL (out), I2C_SDA (bidir), RESET# (bidir), PH1, PH0, SHIELD, SAI1_SDB (out), SAI1_MCKB (out), SAI1_SCKB (out), SAI1_FSB (out), MC_ICL_Shutout (out), MC_PFC_PWM (out), MC_CurrentB (in), MC_CurrentC (in), MC_CurrentA (in), MC_PFC_IndCurr (in), MC_BusVoltage (in), MC_PWM_1H (out), SHIELD_CS, MC_PWM_2H (out), MC_PWM_3H (out), MC_EmergencySTOP (in), A[0..15] (out), LCDSEG[18..20] (bidir), LCDCOM[4..6] (bidir), LCDSEG[22..27] (bidir), BOOT0, NFC_NSS (out)

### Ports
A[0..23] (out), ADC_DAC (bidir), BL_Control (out), BOOT0, Bootloader_BOOT0_3V3 (in), Bootloader_RESET_3V3 (in), CAN_RX (in), CAN_TX (out), CODEC_INT (in), Comp2_INP (in), Comp2_OUT (out), D[0..15] (bidir), DFSDM_CKOUT (out), DFSDM_DATIN1 (in), DMIC_DATIN (in), EXT_RESET (out), FMC_NBL0 (out), FMC_NBL1 (out), FMC_NE1 (out), FMC_NE2 (out), FMC_NOE (out), FMC_NWAIT (in), FMC_NWE (out), I2C2_SCL (out), I2C2_SDA (bidir), I2C_SCL (out), I2C_SDA (bidir), IDD_CNT_EN (out), IDD_Measurement (in), IDD_WAKEUP (in), IOExpander_X+ (bidir), IOExpander_X- (bidir), IOExpander_Y+ (bidir), IOExpander_Y- (bidir), JOY_DOWN (in), JOY_LEFT (in), JOY_RIGHT (in), JOY_SEL (in), JOY_UP (in), Key (in), LCD_NE3 (out), LED1 (out), LED2 (out), LED3 (out), LED4 (out), LPUART_RX_3V3 (in), LPUART_TX (out), MC_BusVoltage (in), MC_CurrentA (in), MC_CurrentB (in), MC_CurrentC (in), MC_DissipativeBrake (out), MC_EmergencySTOP (in), MC_EncA (in), MC_EncB (in), MC_EncIndex (in), MC_ICL_Shutout (out), MC_PFC_IndCurr (in), MC_PFC_PWM (out), MC_PFC_Shutdown (in), MC_PFC_sync (out), MC_PFC_Vac (out), MC_PWM_1H (out), MC_PWM_1L (out), MC_PWM_2H (out), MC_PWM_2L (out), MC_PWM_3H (out), MC_PWM_3L (out), MC_Temperature (in), NFC_MISO (in), NFC_MOSI (out), NFC_NSS (out), NFC_SCK (out), OpAmp1_INM (in), OpAmp1_INP (in), OpAmp1_OUT (out), PA[0..15] (bidir), PB[0..15] (bidir), PC[0..15] (bidir), PD[0..15] (bidir), PE[0..15] (bidir), PF[0..15] (bidir), PG[0..15] (bidir), PH0, PH1, PT100_DATIN (in), QSPI_CLK (out), QSPI_CS (out), QSPI_D0 (bidir), QSPI_D1 (bidir), QSPI_D2 (bidir), QSPI_D3 (bidir), RESET# (bidir), SAI1_FSB (out), SAI1_MCKB (out), SAI1_SCKB (out), SAI1_SDA (in), SAI1_SDB (out), SHIELD, SHIELD_CS, SmartCard_3/5V (out), SmartCard_CLK (out), SmartCard_CMDVCC (out), SmartCard_IO (bidir), SmartCard_OFF (in), SmartCard_RST (out), SWP_IO (bidir), TCK/SWCLK (in), TDI (in), TDO/SWO (out), TKEY, TKEY_CS, TMS/SWDIO (in), TRACE_CK (out), TRACE_D0 (out), TRACE_D1 (out), TRACE_D2 (out), TRACE_D3 (out), TRST (in), USART1/IrDA_RX_3V3 (in), USART1_CTS_3V3 (in), USART1_RTS (out), USART1_TX (out), USBOTG_DM (bidir), USBOTG_DP (bidir), USBOTG_ID (in), USBOTG_OVRCR (in), USBOTG_PPWR (out), USBOTG_PRDY (in), USBOTG_VBUS (in), uSD_CLK (out), uSD_CMD (out), uSD_D0 (bidir), uSD_D1 (bidir), uSD_D2 (bidir), uSD_D3 (bidir), uSD_DETECT (in)

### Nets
BOOT0: port BOOT0, sheet U_MCU2/BOOT0
Comp2_INP: port Comp2_INP, sheet U_LCD_Glass/Comp2_INP
Comp2_OUT: port Comp2_OUT, sheet U_LCD_Glass/Comp2_OUT
I2C_SCL: port I2C_SCL, sheet U_IO_Expandor/I2C_SCL, sheet U_MCU2/I2C_SCL
I2C_SDA: port I2C_SDA, sheet U_IO_Expandor/I2C_SDA, sheet U_MCU2/I2C_SDA
LCD_NE3: port LCD_NE3, sheet U_MCU2/LCD_NE3
LCDSEG7: port TDO/SWO, sheet U_MCU/TDO/SWO
LCDSEG8: port TRST, sheet U_MCU/TRST
LCDSEG17: port TDI, sheet U_MCU/TDI
OpAmp1_INM: port OpAmp1_INM, sheet U_LCD_Glass/OpAmp1_INM
OpAmp1_INP: port OpAmp1_INP, sheet U_MCU/OpAmp1_INP
OpAmp1_OUT: port OpAmp1_OUT, sheet U_LCD_Glass/OpAmp1_OUT
PA4: port ADC_DAC, sheet U_MCU/ADC_DAC
PA11: port USBOTG_DM, sheet U_MCU/USBOTG_DM
PA12: port USBOTG_DP, sheet U_MCU/USBOTG_DP
PA13: port TMS/SWDIO, sheet U_MCU/TMS/SWDIO
PA14: port TCK/SWCLK, sheet U_MCU/TCK/SWCLK
PB6: port USART1_TX, sheet U_MCU/USART1_TX
PC13: port Key, sheet U_MCU2/Key
PD3: port DFSDM_DATIN1, sheet U_MCU/DFSDM_DATIN1
PD4: port FMC_NOE, sheet U_MCU/FMC_NOE
PD5: port FMC_NWE, sheet U_MCU/FMC_NWE
PD7: port FMC_NE1, sheet U_MCU/FMC_NE1
PF11: port NFC_NSS, sheet U_MCU2/NFC_NSS
PG8: port LPUART_RX_3V3, sheet U_MCU2/LPUART_RX_3V3
PG9: port FMC_NE2, sheet U_MCU2/FMC_NE2
PG11: port USART1_CTS_3V3, sheet U_MCU2/USART1_CTS_3V3
PG12: port USART1_RTS, sheet U_MCU2/USART1_RTS
PG15: sheet U_IO_Expandor/IOExpander_INT, sheet U_MCU2/IOExpander_INT
PH0: port PH0, sheet U_MCU2/PH0
PH1: port PH1, sheet U_MCU2/PH1
RESET#: port RESET#, sheet U_MCU/RESET#, sheet U_MCU2/RESET#
NetB3_1: port JOY_LEFT, sheet U_IO_Expandor/JOY_LEFT
NetB3_2: port JOY_SEL, sheet U_IO_Expandor/JOY_SEL
NetB3_3: port JOY_DOWN, sheet U_IO_Expandor/JOY_DOWN
NetB3_4: port JOY_RIGHT, sheet U_IO_Expandor/JOY_RIGHT
NetB3_6: port JOY_UP, sheet U_IO_Expandor/JOY_UP
NetC1_2: port MC_EncB, sheet U_MCU/MC_EncB
NetC2_2: port MC_EncIndex, sheet U_MCU/MC_EncIndex
NetC3_1: port MC_PFC_IndCurr, sheet U_MCU2/MC_PFC_IndCurr
NetC4_2: port MC_EncA, sheet U_MCU/MC_EncA
NetC5_2: port MC_PFC_Shutdown, sheet U_MCU/MC_PFC_Shutdown
NetC6_2: port MC_PFC_Vac, sheet U_MCU/MC_PFC_Vac
NetC7_2: port MC_EmergencySTOP, sheet U_MCU2/MC_EmergencySTOP
NetC9_2: port MC_PFC_PWM, sheet U_MCU2/MC_PFC_PWM
NetC10_2: port MC_CurrentC, sheet U_MCU2/MC_CurrentC
NetC11_1: port MC_BusVoltage, sheet U_MCU2/MC_BusVoltage
NetC13_2: port MC_CurrentB, sheet U_MCU2/MC_CurrentB
NetC14_2: port MC_CurrentA, sheet U_MCU2/MC_CurrentA
NetC15_1: port USBOTG_VBUS, port USBOTG_PRDY, sheet U_LCD_Glass/USBOTG_VBUS, sheet U_LCD_Glass/USBOTG_PRDY
NetC16_2: port MC_PFC_sync, sheet U_MCU2/MC_PFC_sync
NetC17_1: port MC_Temperature, sheet U_MCU/MC_Temperature
NetC34_2: port SHIELD_CS, sheet U_MCU2/SHIELD_CS
NetC37_2: port TKEY_CS, sheet U_MCU/TKEY_CS
NetC73_1: port IDD_Measurement, sheet U_MCU/IDD_Measurement
NetCN2_3: port MC_PWM_1H, sheet U_MCU2/MC_PWM_1H
NetCN2_5: port MC_PWM_1L, sheet U_MCU/MC_PWM_1L
NetCN2_7: port MC_PWM_2H, sheet U_MCU2/MC_PWM_2H
NetCN2_9: port MC_PWM_2L, sheet U_MCU/MC_PWM_2L
NetCN2_11: port MC_PWM_3H, sheet U_MCU2/MC_PWM_3H
NetCN2_13: port MC_PWM_3L, sheet U_MCU/MC_PWM_3L
NetCN2_21: port MC_ICL_Shutout, sheet U_MCU2/MC_ICL_Shutout
NetCN2_23: port MC_DissipativeBrake, sheet U_MCU/MC_DissipativeBrake
NetCN3_4: port EXT_RESET, sheet U_IO_Expandor/EXT_RESET
NetCN11_4: port uSD_DETECT, sheet U_LCD_Glass/uSD_DETECT
NetCN11_6: port USBOTG_ID, sheet U_LCD_Glass/USBOTG_ID
NetCN11_8: port CAN_TX, sheet U_LCD_Glass/CAN_TX
NetCN11_16: port NFC_MISO, sheet U_LCD_Glass/NFC_MISO
NetCN11_18: port NFC_SCK, sheet U_LCD_Glass/NFC_SCK
NetCN11_20: port SWP_IO, sheet U_LCD_Glass/SWP_IO
NetCN11_24: port CAN_RX, sheet U_LCD_Glass/CAN_RX
NetCN11_26: port NFC_MOSI, sheet U_LCD_Glass/NFC_MOSI
NetCN11_28: port DFSDM_CKOUT, sheet U_LCD_Glass/DFSDM_CKOUT
NetCN11_30: port LED3, sheet U_LCD_Glass/LED3
NetCN11_32: port DMIC_DATIN, sheet U_LCD_Glass/DMIC_DATIN
NetCN12_12: port TRACE_CK, sheet U_MCU/TRACE_CK
NetCN12_18: port TRACE_D2, sheet U_MCU/TRACE_D2
NetCN12_20: port TRACE_D3, sheet U_MCU/TRACE_D3
NetCN14_2: port uSD_CMD, sheet U_LCD_Glass/uSD_CMD
NetCN14_10: port USART1/IrDA_RX_3V3, sheet U_LCD_Glass/USART1/IrDA_RX_3V3
NetCN14_40: port FMC_NBL0, sheet U_LCD_Glass/FMC_NBL0
NetCN14_42: port FMC_NBL1, sheet U_LCD_Glass/FMC_NBL1
NetCN18_1: port uSD_D2, sheet U_LCD_Glass/uSD_D2
NetCN18_2: port uSD_D3, sheet U_LCD_Glass/uSD_D3
NetCN18_5: port uSD_CLK, sheet U_LCD_Glass/uSD_CLK
NetCN18_7: port uSD_D0, sheet U_LCD_Glass/uSD_D0
NetCN18_8: port uSD_D1, sheet U_LCD_Glass/uSD_D1
NetCN19_31: port IOExpander_X-, sheet U_IO_Expandor/IOExpander_X-
NetCN19_32: port IOExpander_X+, sheet U_IO_Expandor/IOExpander_X+
NetCN19_33: port IOExpander_Y-, sheet U_IO_Expandor/IOExpander_Y-
NetCN19_34: port IOExpander_Y+, sheet U_IO_Expandor/IOExpander_Y+
NetD4_2: port Bootloader_RESET_3V3, sheet U_MCU2/Bootloader_RESET_3V3
NetJP19_1: port USBOTG_PPWR, sheet U_LCD_Glass/USBOTG_PPWR
NetLD6_2: port USBOTG_OVRCR, sheet U_LCD_Glass/USBOTG_OVRCR
NetR24_1: port PT100_DATIN, sheet U_LCD_Glass/PT100_DATIN
NetR32_2: port FMC_NWAIT, sheet U_MCU/FMC_NWAIT
NetR34_1: port LPUART_TX, sheet U_MCU2/LPUART_TX
NetR35_1: port CODEC_INT, sheet U_MCU2/CODEC_INT
NetR37_1: port SHIELD, sheet U_MCU2/SHIELD
NetR39_1: port TKEY, sheet U_MCU/TKEY
NetR53_2: port SAI1_SDA, sheet U_MCU/SAI1_SDA
NetR54_2: port LED1, sheet U_MCU/LED1
NetR59_2: port Bootloader_BOOT0_3V3, sheet U_MCU2/Bootloader_BOOT0_3V3
NetR71_2: port QSPI_CS, sheet U_MCU/QSPI_CS
NetR89_1: port SAI1_SCKB, sheet U_MCU2/SAI1_SCKB
NetR90_1: port SAI1_FSB, sheet U_MCU2/SAI1_FSB
NetR91_1: port IDD_CNT_EN, sheet U_MCU2/IDD_CNT_EN
NetR104_1: port TRACE_D0, sheet U_MCU/TRACE_D0
NetR105_1: port SAI1_SDB, sheet U_MCU2/SAI1_SDB
NetR106_1: port SAI1_MCKB, sheet U_MCU2/SAI1_MCKB
NetR107_1: port SmartCard_CLK, sheet U_LCD_Glass/SmartCard_CLK
NetR137_1: port IDD_WAKEUP, sheet U_LCD_Glass/IDD_WAKEUP
NetR143_1: port SmartCard_IO, sheet U_LCD_Glass/SmartCard_IO
NetR156_2: port TRACE_D1, sheet U_MCU/TRACE_D1
NetR213_1: port SmartCard_OFF, sheet U_IO_Expandor/SmartCard_OFF
NetR214_2: port SmartCard_RST, sheet U_IO_Expandor/SmartCard_RST
NetR215_2: port SmartCard_CMDVCC, sheet U_IO_Expandor/SmartCard_CMDVCC
NetR241_1: port SmartCard_3/5V, sheet U_IO_Expandor/SmartCard_3/5V
NetR255_1: port LED4, sheet U_IO_Expandor/LED4
NetR257_1: port LED2, sheet U_IO_Expandor/LED2
NetR260_1: port BL_Control, sheet U_IO_Expandor/BL_Control
NetR263_2: port I2C2_SDA, sheet U_LCD_Glass/I2C2_SDA
NetR264_2: port I2C2_SCL, sheet U_LCD_Glass/I2C2_SCL
NetSB9_1: port QSPI_CLK, sheet U_MCU/QSPI_CLK
NetSB12_1: port QSPI_D0, sheet U_MCU/QSPI_D0
NetSB14_1: port QSPI_D1, sheet U_MCU/QSPI_D1
NetSB18_1: port QSPI_D2, sheet U_MCU/QSPI_D2
NetSB21_1: port QSPI_D3, sheet U_MCU/QSPI_D3

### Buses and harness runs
bus A[0..15] = sheet U_MCU2/A[0..15]
bus A[0..23] = port A[0..23]
bus A[16..19] = sheet U_LCD_Glass/A[16..19]
bus A[20..22] = sheet U_MCU/A[20..22]
bus D[0..15] = port D[0..15]
bus D[0..15] = sheet U_LCD_Glass/D[0..15]
bus D[0..15] = sheet U_MCU2/D[0..15]
bus D[0..15] = sheet U_MCU/D[0..15]
bus LCDCOM[0..3] = sheet U_MCU/LCDCOM[0..3]
bus LCDCOM[0..7] = sheet U_LCD_Glass/LCDCOM[0..7]
bus LCDCOM[4..6] = sheet U_MCU2/LCDCOM[4..6]
bus LCDSEG[0..17] = sheet U_MCU/LCDSEG[0..17]
bus LCDSEG[0..39] = sheet U_LCD_Glass/LCDSEG[0..39]
bus LCDSEG[18..20] = sheet U_MCU2/LCDSEG[18..20]
bus LCDSEG[22..27] = sheet U_MCU2/LCDSEG[22..27]
bus LCDSEG[28..39] = sheet U_MCU/LCDSEG[28..39]
bus port PA[0..15] = sheet U_MCU/PA[0..15]
bus port PB[0..15] = sheet U_MCU/PB[0..15]
bus port PC[0..15] = sheet U_MCU2/PC[0..15]
bus port PD[0..15] = sheet U_MCU/PD[0..15]
bus port PE[0..15] = sheet U_MCU/PE[0..15]
bus port PF[0..15] = sheet U_MCU2/PF[0..15]
bus port PG[0..15] = sheet U_MCU2/PG[0..15]

## Sheet MCU.SchDoc: MCU
size A3; DocumentNumber: MB1144; Revision: B-02; SheetNumber: 3; SheetTotal: 25; PageSetup: Record=PageOptions|CenterHorizontal=True|CenterVertical=True|PrintScale=1.04|XCorrection=1.00|YCorrection=1.00|PrintKind=1|BorderSize=5000000|LeftOffset=0|BottomOffset=0|Orientation=2|PaperLength=1000|PaperWidth=1000|Scale=100|PaperSource=7|PrintQuality=600|MediaType=1|DitherType=10|PaperKind=A3|PrintScaleMode=1; Project: STM32L476G-EVAL
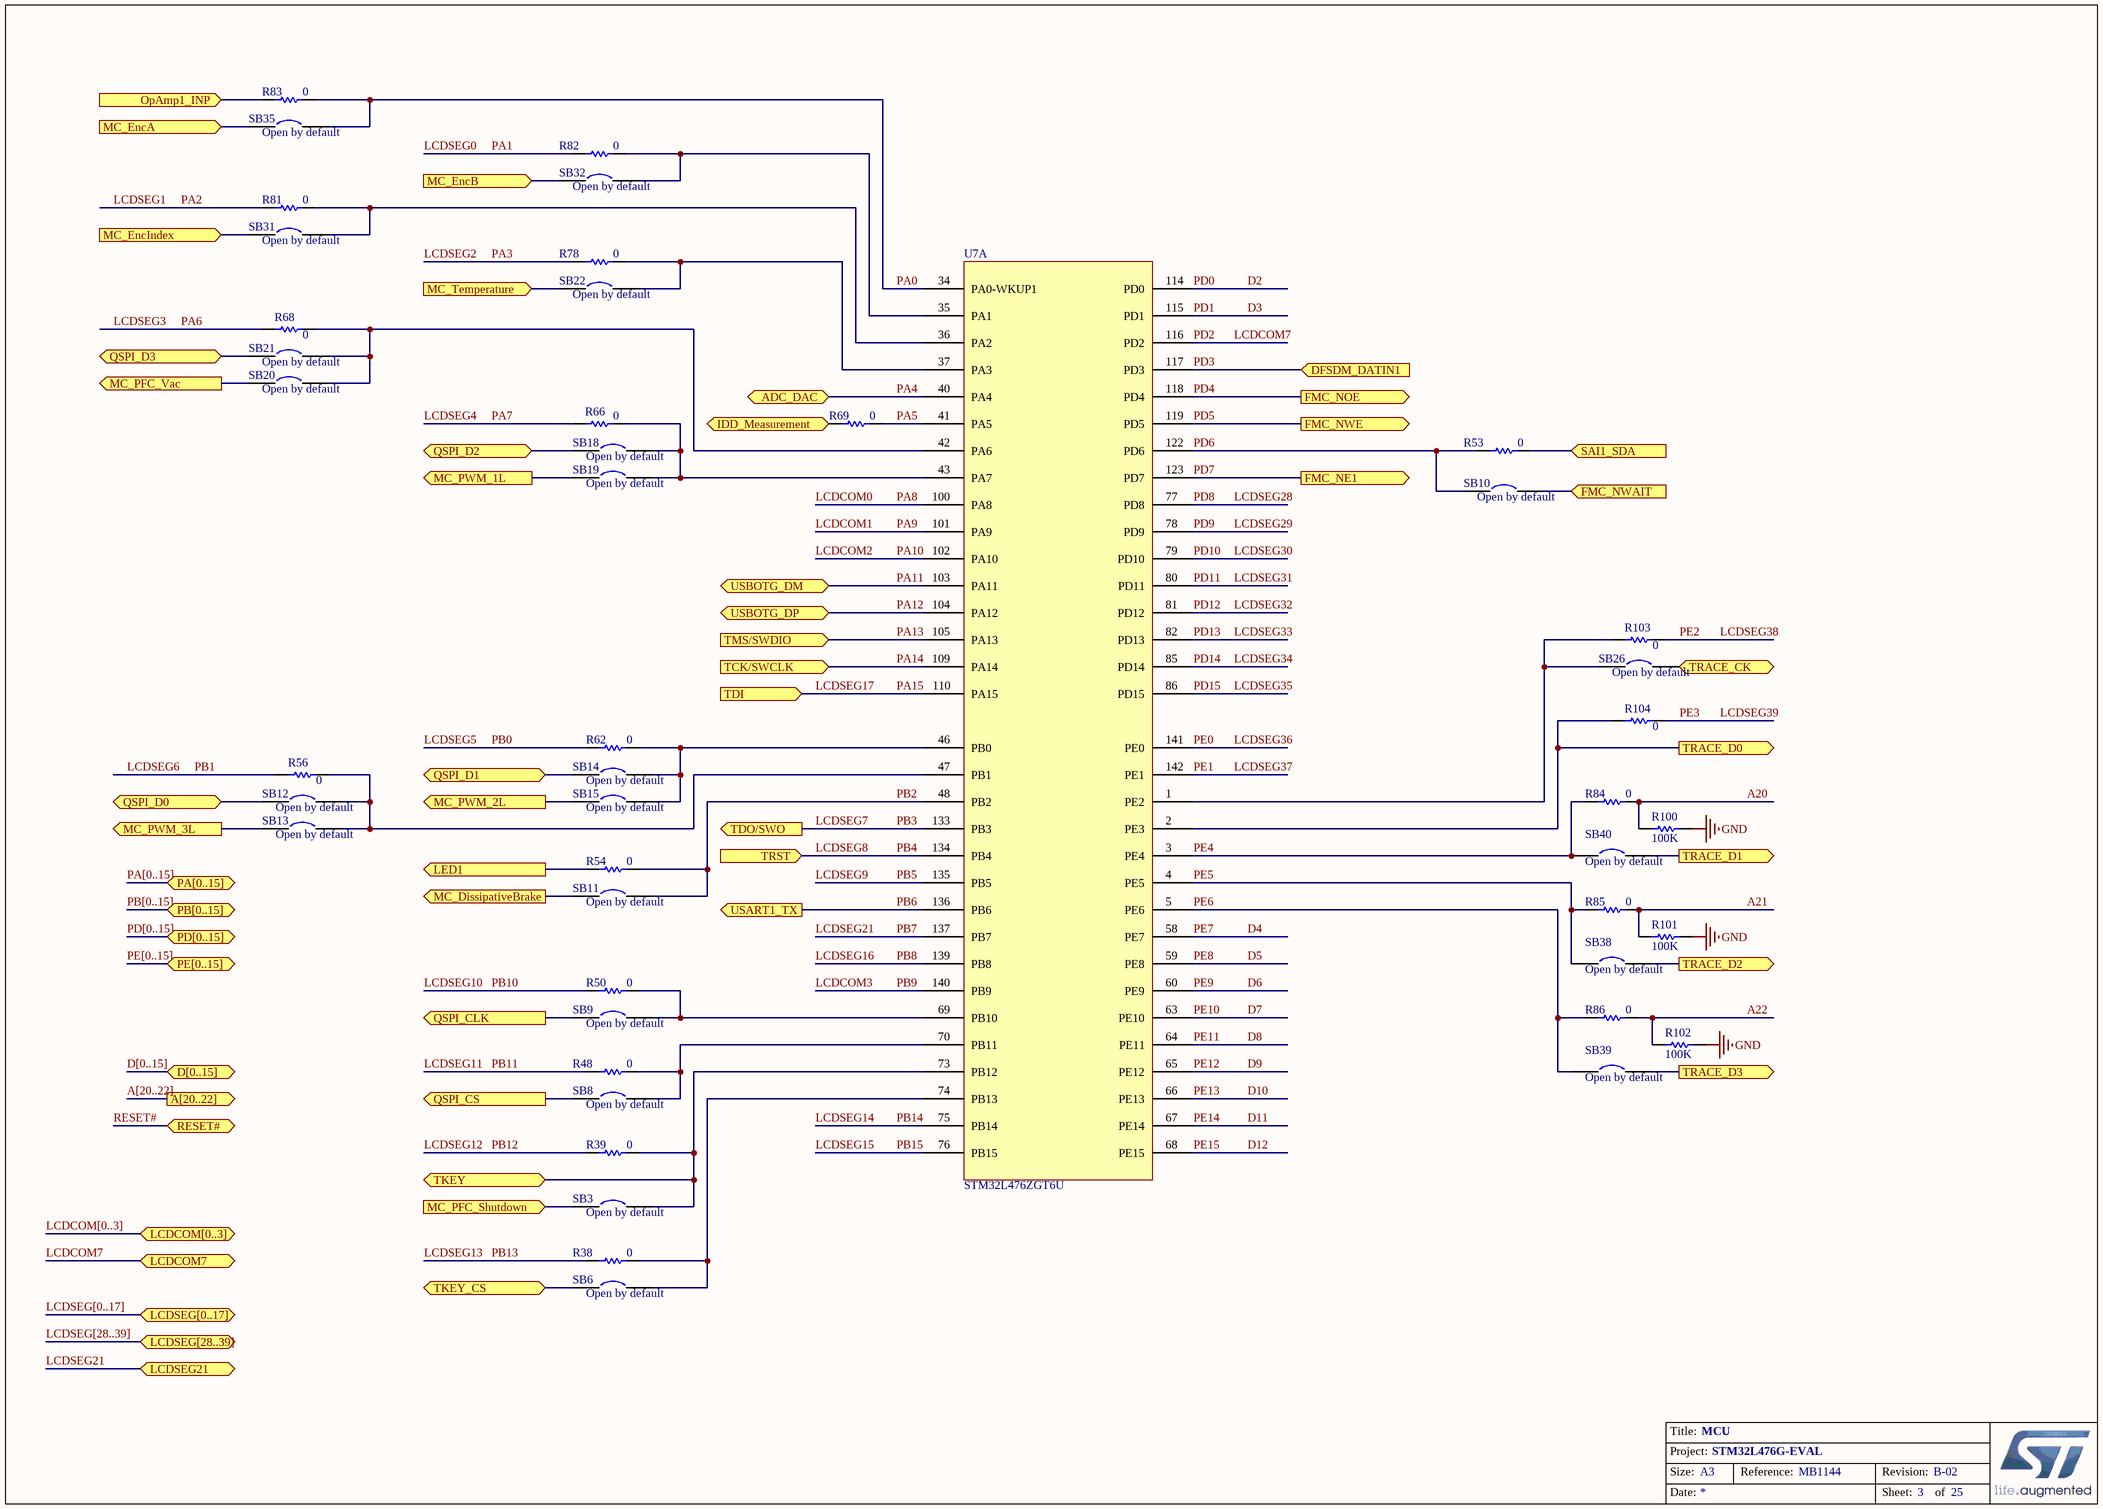
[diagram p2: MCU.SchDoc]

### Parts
R38  0  [SB_0603]
R39  0  [SB_0603]
R48  0  [SB_0603]
R50  0  [SB_0603]
R53  0  [SB_0603]
R54  0  [SB_0603]
R56  0  [SB_0603]
R62  0  [SB_0603]
R66  0  [SB_0603]
R68  0  [SB_0603]
R69  0  [0603R]
R78  0  [SB_0603]
R81  0  [SB_0603]
R82  0  [SB_0603]
R83  0  [SB_0603]
R84  0  [SB_0603]
R85  0  [SB_0603]
R86  0  [SB_0603]
R100  100K  [0402R]
R101  100K  [0402R]
R102  100K  [0402R]
R103  0  [SB_0603]
R104  0  [SB_0603]
SB3  Open by default  [SB_0603]
SB6  Open by default  [SB_0603]
SB8  Open by default  [SB_0603]
SB9  Open by default  [SB_0603]
SB10  Open by default  [SB_0603]
SB11  Open by default  [SB_0603]
SB12  Open by default  [SB_0603]
SB13  Open by default  [SB_0603]
SB14  Open by default  [SB_0603]
SB15  Open by default  [SB_0603]
SB18  Open by default  [SB_0603]
SB19  Open by default  [SB_0603]
SB20  Open by default  [SB_0603]
SB21  Open by default  [SB_0603]
SB22  Open by default  [SB_0603]
SB26  Open by default  [SB_0603]
SB31  Open by default  [SB_0603]
SB32  Open by default  [SB_0603]
SB35  Open by default  [SB_0603]
SB38  Open by default  [SB_0603]
SB39  Open by default  [SB_0603]
SB40  Open by default  [SB_0603]
U7  STM32L476ZGT6U  [TQFP144_0R5_22X22_SOCKET]  (part A of 3)

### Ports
A[20..22] (out), ADC_DAC (bidir), D[0..15] (bidir), DFSDM_DATIN1 (in), FMC_NE1 (out), FMC_NOE (out), FMC_NWAIT (in), FMC_NWE (out), IDD_Measurement (in), LCDCOM7, LCDCOM[0..3] (bidir), LCDSEG21 (bidir), LCDSEG[0..17] (bidir), LCDSEG[28..39] (bidir), LED1 (out), MC_DissipativeBrake (out), MC_EncA (in), MC_EncB (in), MC_EncIndex (in), MC_PFC_Shutdown (in), MC_PFC_Vac (out), MC_PWM_1L (out), MC_PWM_2L (out), MC_PWM_3L (out), MC_Temperature (in), OpAmp1_INP (in), PA[0..15] (bidir), PB[0..15] (bidir), PD[0..15] (bidir), PE[0..15] (bidir), QSPI_CLK (out), QSPI_CS (out), QSPI_D0 (bidir), QSPI_D1 (bidir), QSPI_D2 (bidir), QSPI_D3 (bidir), RESET# (bidir), SAI1_SDA (in), TCK/SWCLK (in), TDI (in), TDO/SWO (out), TKEY, TKEY_CS, TMS/SWDIO (in), TRACE_CK (out), TRACE_D0 (out), TRACE_D1 (out), TRACE_D2 (out), TRACE_D3 (out), TRST (in), USART1_TX (out), USBOTG_DM (bidir), USBOTG_DP (bidir)

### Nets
GND: R100.2 R101.2 R102.2
A20: R84.1 R100.1
A21: R85.1 R101.1
A22: R86.1 R102.1
D2: U7.114(PD0)  [also labelled PD0]
D3: U7.115(PD1)  [also labelled PD1]
D4: U7.58(PE7)  [also labelled PE7]
D5: U7.59(PE8)  [also labelled PE8]
D6: U7.60(PE9)  [also labelled PE9]
D7: U7.63(PE10)  [also labelled PE10]
D8: U7.64(PE11)  [also labelled PE11]
D9: U7.65(PE12)  [also labelled PE12]
D10: U7.66(PE13)  [also labelled PE13]
D11: U7.67(PE14)  [also labelled PE14]
D12: U7.68(PE15)  [also labelled PE15]
LCDCOM0: U7.100(PA8)  [also labelled PA8]
LCDCOM1: U7.101(PA9)  [also labelled PA9]
LCDCOM2: U7.102(PA10)  [also labelled PA10]
LCDCOM3: U7.140(PB9)  [also labelled PB9]
LCDCOM7: U7.116(PD2) ; port LCDCOM7  [also labelled PD2]
LCDSEG0: R82.1  [also labelled PA1]
LCDSEG1: R81.1  [also labelled PA2]
LCDSEG2: R78.2  [also labelled PA3]
LCDSEG3: R68.1  [also labelled PA6]
LCDSEG4: R66.1  [also labelled PA7]
LCDSEG5: R62.1  [also labelled PB0]
LCDSEG6: R56.1  [also labelled PB1]
LCDSEG7: U7.133(PB3) ; port TDO/SWO  [also labelled PB3]
LCDSEG8: U7.134(PB4) ; port TRST  [also labelled PB4]
LCDSEG9: U7.135(PB5)  [also labelled PB5]
LCDSEG10: R50.1  [also labelled PB10]
LCDSEG11: R48.1  [also labelled PB11]
LCDSEG12: R39.2  [also labelled PB12]
LCDSEG13: R38.1  [also labelled PB13]
LCDSEG14: U7.75(PB14)  [also labelled PB14]
LCDSEG15: U7.76(PB15)  [also labelled PB15]
LCDSEG16: U7.139(PB8)  [also labelled PB8]
LCDSEG17: U7.110(PA15) ; port TDI  [also labelled PA15]
LCDSEG21: U7.137(PB7) ; port LCDSEG21  [also labelled PB7]
LCDSEG28: U7.77(PD8)  [also labelled PD8]
LCDSEG29: U7.78(PD9)  [also labelled PD9]
LCDSEG30: U7.79(PD10)  [also labelled PD10]
LCDSEG31: U7.80(PD11)  [also labelled PD11]
LCDSEG32: U7.81(PD12)  [also labelled PD12]
LCDSEG33: U7.82(PD13)  [also labelled PD13]
LCDSEG34: U7.85(PD14)  [also labelled PD14]
LCDSEG35: U7.86(PD15)  [also labelled PD15]
LCDSEG36: U7.141(PE0)  [also labelled PE0]
LCDSEG37: U7.142(PE1)  [also labelled PE1]
LCDSEG38: R103.2  [also labelled PE2]
LCDSEG39: R104.2  [also labelled PE3]
OpAmp1_INP: R83.2 ; port OpAmp1_INP
PA0: R83.1 SB35.2 U7.34(PA0-WKUP1)
PA4: U7.40(PA4) ; port ADC_DAC
PA5: R69.1 U7.41(PA5)
PA11: U7.103(PA11) ; port USBOTG_DM
PA12: U7.104(PA12) ; port USBOTG_DP
PA13: U7.105(PA13) ; port TMS/SWDIO
PA14: U7.109(PA14) ; port TCK/SWCLK
PB2: R54.1 SB11.2 U7.48(PB2)
PB6: U7.136(PB6) ; port USART1_TX
PD3: U7.117(PD3) ; port DFSDM_DATIN1
PD4: U7.118(PD4) ; port FMC_NOE
PD5: U7.119(PD5) ; port FMC_NWE
PD6: R53.1 SB10.1 U7.122(PD6)
PD7: U7.123(PD7) ; port FMC_NE1
PE4: R84.2 SB40.1 U7.3(PE4)
PE5: R85.2 SB38.1 U7.4(PE5)
PE6: R86.2 SB39.1 U7.5(PE6)
NetC1_2: SB32.1 ; port MC_EncB
NetC2_2: SB31.1 ; port MC_EncIndex
NetC4_2: SB35.1 ; port MC_EncA
NetC5_2: SB3.1 ; port MC_PFC_Shutdown
NetC6_2: SB20.1 ; port MC_PFC_Vac
NetC17_1: SB22.1 ; port MC_Temperature
NetC37_2: SB6.1 ; port TKEY_CS
NetC73_1: R69.2 ; port IDD_Measurement
NetCN2_5: SB19.1 ; port MC_PWM_1L
NetCN2_9: SB15.1 ; port MC_PWM_2L
NetCN2_13: SB13.1 ; port MC_PWM_3L
NetCN2_23: SB11.1 ; port MC_DissipativeBrake
NetCN12_12: SB26.2 ; port TRACE_CK
NetCN12_18: SB38.2 ; port TRACE_D2
NetCN12_20: SB39.2 ; port TRACE_D3
NetR32_2: SB10.2 ; port FMC_NWAIT
NetR38_2: R38.2 SB6.2 U7.74(PB13)
NetR39_1: R39.1 SB3.2 U7.73(PB12) ; port TKEY
NetR48_2: R48.2 SB8.2 U7.70(PB11)
NetR50_2: R50.2 SB9.2 U7.69(PB10)
NetR53_2: R53.2 ; port SAI1_SDA
NetR54_2: R54.2 ; port LED1
NetR56_2: R56.2 SB12.2 SB13.2 U7.47(PB1)
NetR62_2: R62.2 SB14.2 SB15.2 U7.46(PB0)
NetR66_2: R66.2 SB18.2 SB19.2 U7.43(PA7)
NetR68_2: R68.2 SB20.2 SB21.2 U7.42(PA6)
NetR71_2: SB8.1 ; port QSPI_CS
NetR78_1: R78.1 SB22.2 U7.37(PA3)
NetR81_2: R81.2 SB31.2 U7.36(PA2)
NetR82_2: R82.2 SB32.2 U7.35(PA1)
NetR103_1: R103.1 SB26.1 U7.1(PE2)
NetR104_1: R104.1 U7.2(PE3) ; port TRACE_D0
NetR156_2: SB40.2 ; port TRACE_D1
NetSB9_1: SB9.1 ; port QSPI_CLK
NetSB12_1: SB12.1 ; port QSPI_D0
NetSB14_1: SB14.1 ; port QSPI_D1
NetSB18_1: SB18.1 ; port QSPI_D2
NetSB21_1: SB21.1 ; port QSPI_D3

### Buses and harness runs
bus A[20..22] = port A[20..22]
bus D[0..15] = port D[0..15]
bus LCDCOM[0..3] = port LCDCOM[0..3]
bus LCDSEG[0..17] = port LCDSEG[0..17]
bus LCDSEG[28..39] = port LCDSEG[28..39]
bus PA[0..15] = port PA[0..15]
bus PB[0..15] = port PB[0..15]
bus PD[0..15] = port PD[0..15]
bus PE[0..15] = port PE[0..15]

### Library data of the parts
R38 R48 R50 R53 R56 R62 R66 R68 R81 R82 R103 R104 = Res1: Resistor; Value: 1K; Ordered by: Subcon; ECCN_US/EU: NA
R39 R54 R69 R78 R83-R86 R100-R102 = res1: Resistor; Value: 1K; Ordered by: Subcon; ECCN_US/EU: NA
SB3 SB6 SB8-SB15 SB18-SB22 SB26 SB31 SB32 SB35 SB38-SB40 = Circuit Breaker: Ordered by: Subcon; Comments: Solder bridge; Fitted: NO; ECCN_US/EU: NA
U7 = STM32L476_TQFP144: Manuf_Part_1: STM32L476ZGT6U cut1.3; Ordered by: ST; ECCN_US/EU: 3A991A2/NEC; Assembly: MCU; Ref St: 9175195

## Sheet LCD_Glass.SchDoc: LCD_Glass
size A3; DocumentNumber: MB1144; Revision: B-02; SheetNumber: 5; SheetTotal: 25; PageSetup: Record=PageOptions|CenterHorizontal=True|CenterVertical=True|PrintScale=1.04|XCorrection=1.00|YCorrection=1.00|PrintKind=1|BorderSize=5000000|LeftOffset=0|BottomOffset=0|Orientation=2|PaperLength=1000|PaperWidth=1000|Scale=100|PaperSource=7|PrintQuality=600|MediaType=1|DitherType=10|PaperKind=A3|PrintScaleMode=1; Project: STM32L476G-EVAL
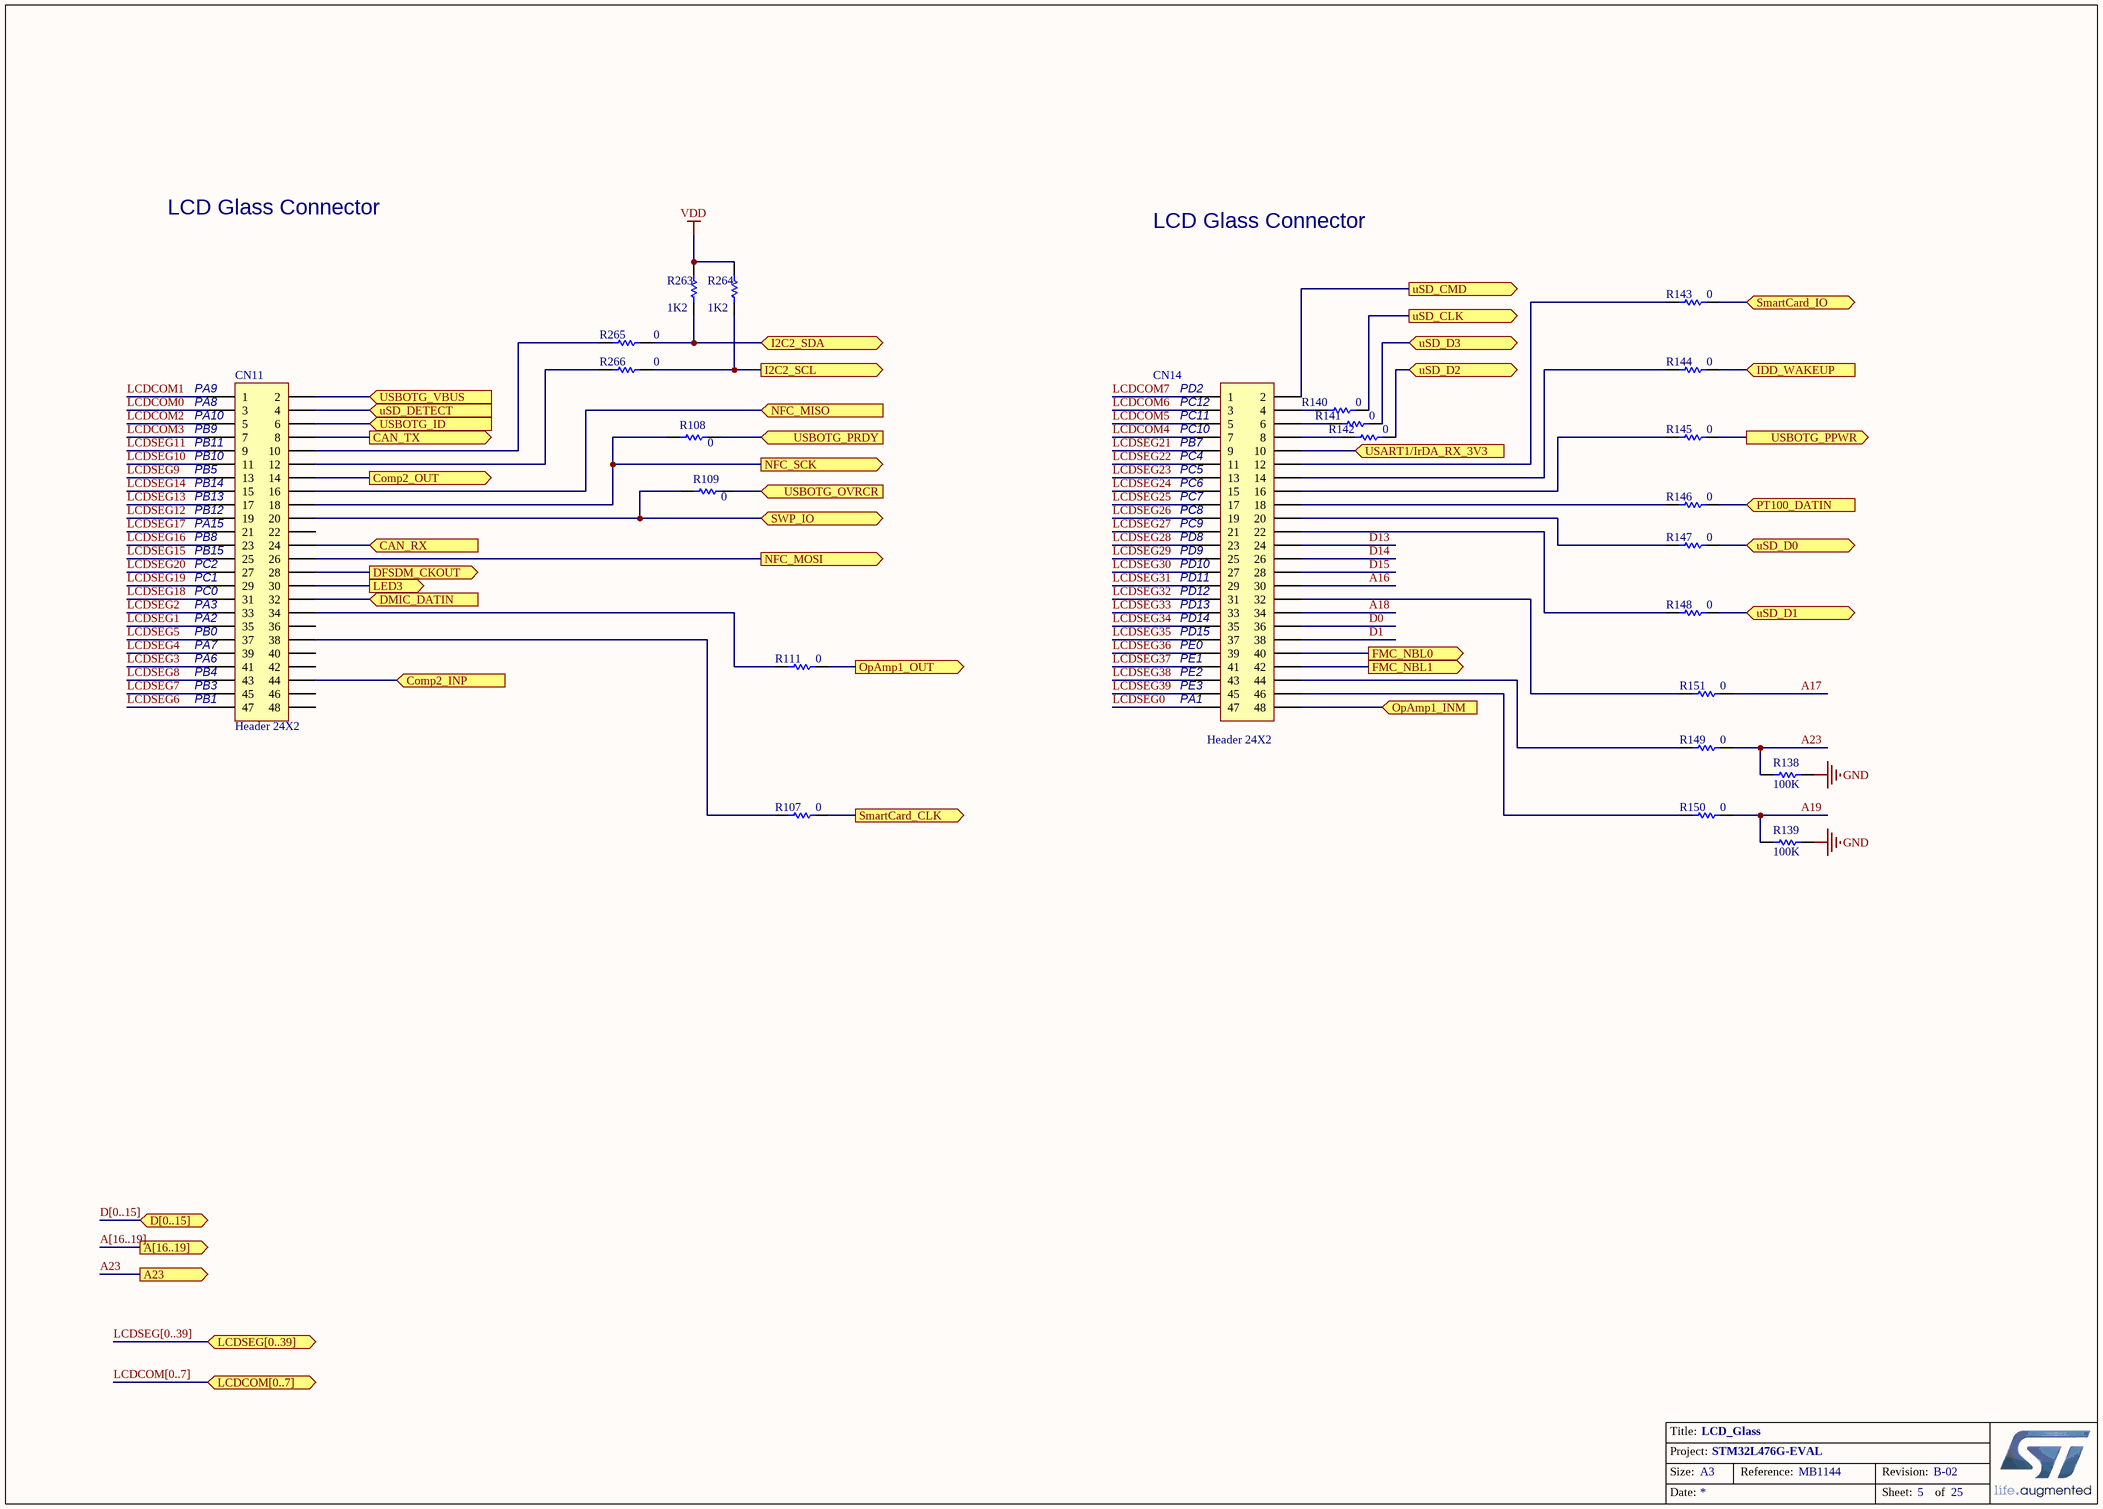
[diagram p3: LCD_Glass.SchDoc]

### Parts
CN11  Header 24X2  [HDR_2X24_2R54]
CN14  Header 24X2  [HDR_2X24_2R54]
R107  0  [0603R]
R108  0  [SB_0603]
R109  0  [SB_0603]
R111  0  [0603R]
R138  100K  [0402R]
R139  100K  [0402R]
R140  0  [0603R]
R141  0  [0603R]
R142  0  [0603R]
R143  0  [0603R]
R144  0  [0603R]
R145  0  [0603R]
R146  0  [0603R]
R147  0  [0603R]
R148  0  [0603R]
R149  0  [0603R]
R150  0  [0603R]
R151  0  [0603R]
R263  1K2  [0402R]
R264  1K2  [0402R]
R265  0  [0603R]
R266  0  [0603R]

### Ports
A23 (out), A[16..19] (out), CAN_RX (in), CAN_TX (out), Comp2_INP (in), Comp2_OUT (out), D[0..15] (bidir), DFSDM_CKOUT (out), DMIC_DATIN (in), FMC_NBL0 (out), FMC_NBL1 (out), I2C2_SCL (out), I2C2_SDA (bidir), IDD_WAKEUP (in), LCDCOM[0..7] (bidir), LCDSEG[0..39] (bidir), LED3 (out), NFC_MISO (in), NFC_MOSI (out), NFC_SCK (out), OpAmp1_INM (in), OpAmp1_OUT (out), PT100_DATIN (in), SmartCard_CLK (out), SmartCard_IO (bidir), SWP_IO (bidir), USART1/IrDA_RX_3V3 (in), USBOTG_ID (in), USBOTG_OVRCR (in), USBOTG_PPWR (out), USBOTG_PRDY (in), USBOTG_VBUS (in), uSD_CLK (out), uSD_CMD (out), uSD_D0 (bidir), uSD_D1 (bidir), uSD_D2 (bidir), uSD_D3 (bidir), uSD_DETECT (in)

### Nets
GND: R138.2 R139.2
VDD: R263.1 R264.1
A16: CN14.30
A17: R151.1
A18: CN14.34
A19: R139.1 R150.1
A23: R138.1 R149.1 ; port A23
Comp2_INP: CN11.44 ; port Comp2_INP
Comp2_OUT: CN11.14 ; port Comp2_OUT
D0: CN14.36
D1: CN14.38
D13: CN14.24
D14: CN14.26
D15: CN14.28
LCDCOM0: CN11.3
LCDCOM1: CN11.1
LCDCOM2: CN11.5
LCDCOM3: CN11.7
LCDCOM4: CN14.7
LCDCOM5: CN14.5
LCDCOM6: CN14.3
LCDCOM7: CN14.1
LCDSEG0: CN14.47
LCDSEG1: CN11.35
LCDSEG2: CN11.33
LCDSEG3: CN11.41
LCDSEG4: CN11.39
LCDSEG5: CN11.37
LCDSEG6: CN11.47
LCDSEG7: CN11.45
LCDSEG8: CN11.43
LCDSEG9: CN11.13
LCDSEG10: CN11.11
LCDSEG11: CN11.9
LCDSEG12: CN11.19
LCDSEG13: CN11.17
LCDSEG14: CN11.15
LCDSEG15: CN11.25
LCDSEG16: CN11.23
LCDSEG17: CN11.21
LCDSEG18: CN11.31
LCDSEG19: CN11.29
LCDSEG20: CN11.27
LCDSEG21: CN14.9
LCDSEG22: CN14.11
LCDSEG23: CN14.13
LCDSEG24: CN14.15
LCDSEG25: CN14.17
LCDSEG26: CN14.19
LCDSEG27: CN14.21
LCDSEG28: CN14.23
LCDSEG29: CN14.25
LCDSEG30: CN14.27
LCDSEG31: CN14.29
LCDSEG32: CN14.31
LCDSEG33: CN14.33
LCDSEG34: CN14.35
LCDSEG35: CN14.37
LCDSEG36: CN14.39
LCDSEG37: CN14.41
LCDSEG38: CN14.43
LCDSEG39: CN14.45
OpAmp1_INM: CN14.48 ; port OpAmp1_INM
OpAmp1_OUT: R111.1 ; port OpAmp1_OUT
NetC15_1: CN11.2 R108.2 ; port USBOTG_VBUS, port USBOTG_PRDY
NetCN11_4: CN11.4 ; port uSD_DETECT
NetCN11_6: CN11.6 ; port USBOTG_ID
NetCN11_8: CN11.8 ; port CAN_TX
NetCN11_10: CN11.10 R265.2
NetCN11_12: CN11.12 R266.2
NetCN11_16: CN11.16 ; port NFC_MISO
NetCN11_18: CN11.18 R108.1 ; port NFC_SCK
NetCN11_20: CN11.20 R109.1 ; port SWP_IO
NetCN11_24: CN11.24 ; port CAN_RX
NetCN11_26: CN11.26 ; port NFC_MOSI
NetCN11_28: CN11.28 ; port DFSDM_CKOUT
NetCN11_30: CN11.30 ; port LED3
NetCN11_32: CN11.32 ; port DMIC_DATIN
NetCN11_34: CN11.34 R111.2
NetCN11_38: CN11.38 R107.2
NetCN14_2: CN14.2 ; port uSD_CMD
NetCN14_4: CN14.4 R140.2
NetCN14_6: CN14.6 R141.2
NetCN14_8: CN14.8 R142.2
NetCN14_10: CN14.10 ; port USART1/IrDA_RX_3V3
NetCN14_12: CN14.12 R143.2
NetCN14_14: CN14.14 R144.2
NetCN14_16: CN14.16 R145.2
NetCN14_18: CN14.18 R146.2
NetCN14_20: CN14.20 R147.2
NetCN14_22: CN14.22 R148.2
NetCN14_32: CN14.32 R151.2
NetCN14_40: CN14.40 ; port FMC_NBL0
NetCN14_42: CN14.42 ; port FMC_NBL1
NetCN14_44: CN14.44 R149.2
NetCN14_46: CN14.46 R150.2
NetCN18_1: R142.1 ; port uSD_D2
NetCN18_2: R141.1 ; port uSD_D3
NetCN18_5: R140.1 ; port uSD_CLK
NetCN18_7: R147.1 ; port uSD_D0
NetCN18_8: R148.1 ; port uSD_D1
NetJP19_1: R145.1 ; port USBOTG_PPWR
NetLD6_2: R109.2 ; port USBOTG_OVRCR
NetR24_1: R146.1 ; port PT100_DATIN
NetR107_1: R107.1 ; port SmartCard_CLK
NetR137_1: R144.1 ; port IDD_WAKEUP
NetR143_1: R143.1 ; port SmartCard_IO
NetR263_2: R263.2 R265.1 ; port I2C2_SDA
NetR264_2: R264.2 R266.1 ; port I2C2_SCL

Not connected (* = marked no-connect by the designer): CN11 22 36 40 42 46 48

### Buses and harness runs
bus A[16..19] = port A[16..19]
bus D[0..15] = port D[0..15]
bus LCDCOM[0..7] = port LCDCOM[0..7]
bus LCDSEG[0..39] = port LCDSEG[0..39]

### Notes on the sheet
- LCD Glass Connector
- (near CN11) PA9
- (near CN11) PA8
- (near CN11) PA10
- (near CN11) PB9
- (near CN11) PB11
- (near CN14) PD2
- (near CN14) PC12
- (near CN14) PC11
- (near CN14) PC10
- (near CN14) PB7
- (near CN11) PB10
- (near CN11) PB5
- (near CN11) PB14
- (near CN11) PB13
- (near CN11) PB12
- (near CN14) PC4
- (near CN14) PC5
- (near CN14) PC6
- (near CN14) PC7
- (near CN14) PC
- (near CN14) PC8
- (near CN11) PA15
- (near CN11) PB8
- (near CN11) PB15
- (near CN11) PC2
- (near CN11) PC1
- (near CN14) PD11
- (near CN14) PD10
- (near CN14) PD9
- (near CN14) PD8
- (near CN14) PC9
- (near CN11) PA3
- (near CN11) PA2
- (near CN11) PA7
- (near CN11) PB0
- (near CN11) PC0
- (near CN14) PD12
- (near CN14) PD13
- (near CN14) PD14
- (near CN14) PD15
- (near CN14) PE0
- (near CN11) PA6
- (near CN11) PB4
- (near CN11) PB3
- (near CN11) PB1
- (near CN14) PE1
- (near CN14) PE2
- (near CN14) PE3
- (near CN14) PA1

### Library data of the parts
CN11 CN14 = Header 24X2: Header, 24-Pin, Dual row; Ordered by: Subcon; Comments: LCD Glass connector; ECCN_US/EU: NA; Assembly: with MB979
R107 R111 R138-R151 = res1: as R39 on sheet MCU
R108 R109 R263-R266 = Res1: as R38 on sheet MCU

## Sheet IO_Expandor.SchDoc: IO_Expandor
size A3; DocumentNumber: MB1144; Revision: B-02; SheetNumber: 6; SheetTotal: 25; Project: STM32L476G-EVAL
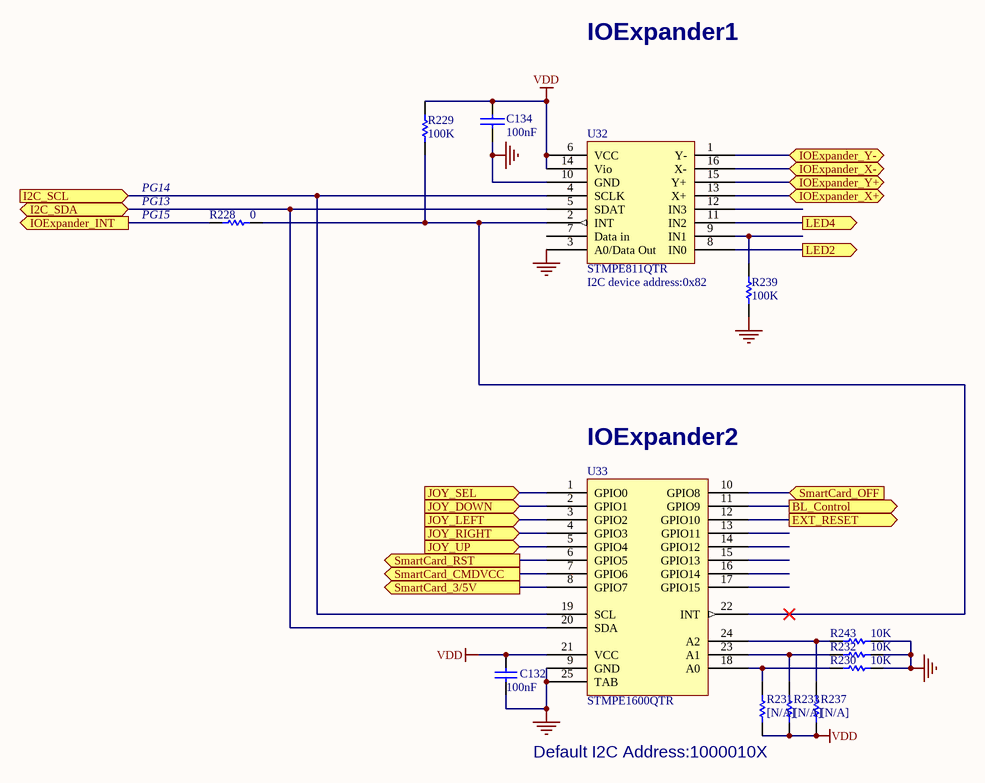
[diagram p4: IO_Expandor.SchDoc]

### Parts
C132  100nF  [0402C]
C134  100nF  [0402C]
R228  0  [0603R]
R229  100K  [0402R]
R230  10K  [0402R]
R231  [N/A]  [0603R]
R232  10K  [0402R]
R233  [N/A]  [0603R]
R237  [N/A]  [0603R]
R239  100K  [0402R]
R243  10K  [0402R]
U32  STMPE811QTR  [QFN16_0R5_3X3]
U33  STMPE1600QTR  [QFN24_0R5_4X4]

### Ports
BL_Control (out), EXT_RESET (out), I2C_SCL (in), I2C_SDA (bidir), IOExpander_INT (out), IOExpander_X+ (bidir), IOExpander_X- (bidir), IOExpander_Y+ (bidir), IOExpander_Y- (bidir), JOY_DOWN (in), JOY_LEFT (in), JOY_RIGHT (in), JOY_SEL (in), JOY_UP (in), LED2 (out), LED4 (out), SmartCard_3/5V (out), SmartCard_CMDVCC (out), SmartCard_OFF (in), SmartCard_RST (out)

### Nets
GND: C132.2 C134.2 R230.1 R232.1 R239.2 R243.1 U32.3(A0/Data_Out) U32.10(GND) U33.9(GND) U33.25(TAB)
VDD: C132.1 C134.1 R229.1 R231.1 R233.1 R237.1 U32.6(VCC) U32.14(Vio) U33.21(VCC)
I2C_SCL: U32.4(SCLK) U33.19(SCL) ; port I2C_SCL
I2C_SDA: U32.5(SDAT) U33.20(SDA) ; port I2C_SDA
PG15: R228.1 ; port IOExpander_INT
NetB3_1: U33.3(GPIO2) ; port JOY_LEFT
NetB3_2: U33.1(GPIO0) ; port JOY_SEL
NetB3_3: U33.2(GPIO1) ; port JOY_DOWN
NetB3_4: U33.4(GPIO3) ; port JOY_RIGHT
NetB3_6: U33.5(GPIO4) ; port JOY_UP
NetCN3_4: U33.12(GPIO10) ; port EXT_RESET
NetCN19_31: U32.16(X-) ; port IOExpander_X-
NetCN19_32: U32.13(X+) ; port IOExpander_X+
NetCN19_33: U32.1(Y-) ; port IOExpander_Y-
NetCN19_34: U32.15(Y+) ; port IOExpander_Y+
NetR213_1: U33.10(GPIO8) ; port SmartCard_OFF
NetR214_2: U33.6(GPIO5) ; port SmartCard_RST
NetR215_2: U33.7(GPIO6) ; port SmartCard_CMDVCC
NetR228_2: R228.2 R229.2 U32.2(INT) U33.22(INT)
NetR230_2: R230.2 R231.2 U33.18(A0)
NetR232_2: R232.2 R233.2 U33.23(A1)
NetR237_2: R237.2 R243.2 U33.24(A2)
NetR239_1: R239.1 U32.9(IN1)
NetR241_1: U33.8(GPIO7) ; port SmartCard_3/5V
NetR255_1: U32.11(IN2) ; port LED4
NetR257_1: U32.8(IN0) ; port LED2
NetR260_1: U33.11(GPIO9) ; port BL_Control

Not connected (* = marked no-connect by the designer): U32 7(Data_in) 12(IN3); U33 13(GPIO11) 14(GPIO12) 15(GPIO13) 16(GPIO14) 17(GPIO15)

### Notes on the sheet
- IOExpander1
- PG13
- PG14
- PG15
- I2C device address:0x82
- (near U33) IOExpander2
- Default I2C Address:1000010X

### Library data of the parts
C132 = Cap: Capacitor; Value: 10nF; Ordered by: Subcon; ECCN_US/EU: NA
C134 = CAP: Capacitor; Ordered by: Subcon; ECCN_US/EU: NA
R228 R229 R239 = Res1: as R38 on sheet MCU
R230 R232 R243 = res1: as R39 on sheet MCU
R231 R233 R237 = Res1: Resistor; Value: 1K; Ordered by: Subcon; ECCN_US/EU: NA; Fitted: NO
U32 = STMPE811: Ordered by: ST; ECCN_US/EU: EAR99/NEC; Ref St: 9177945
U33 = STMPE1600: Ordered by: ST; ECCN_US/EU: EAR99/NEC; Ref St: 9177976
